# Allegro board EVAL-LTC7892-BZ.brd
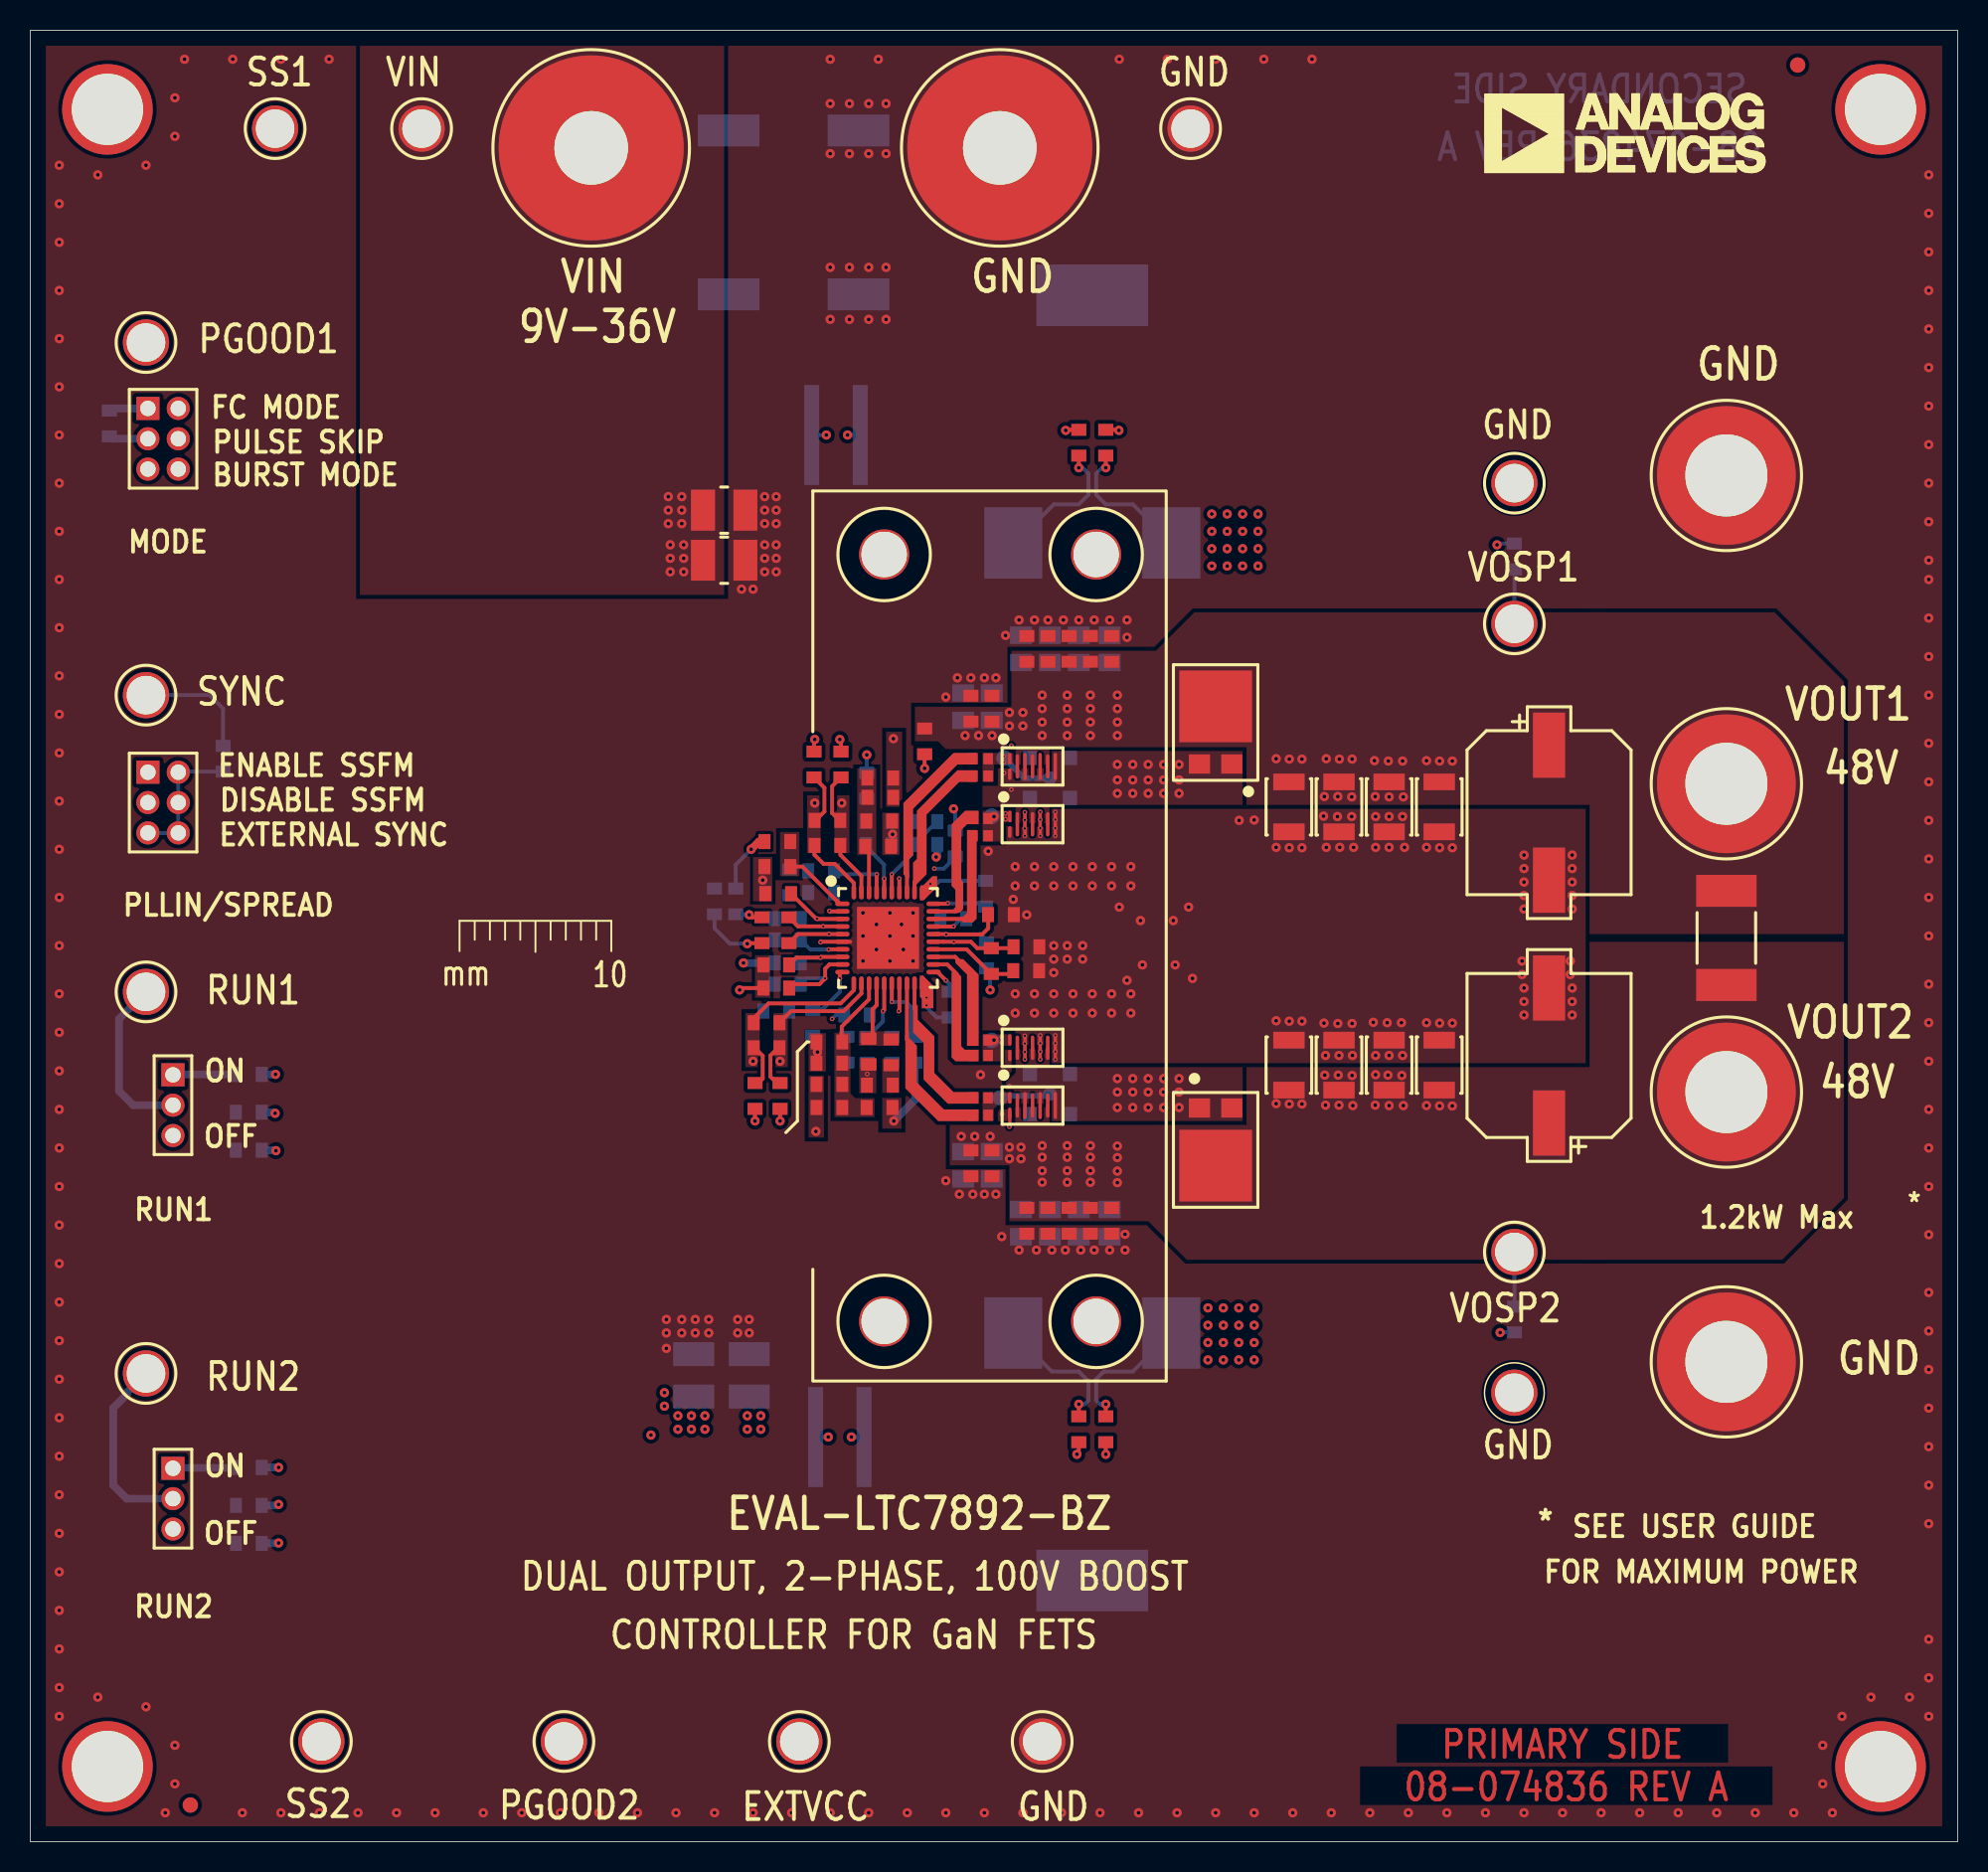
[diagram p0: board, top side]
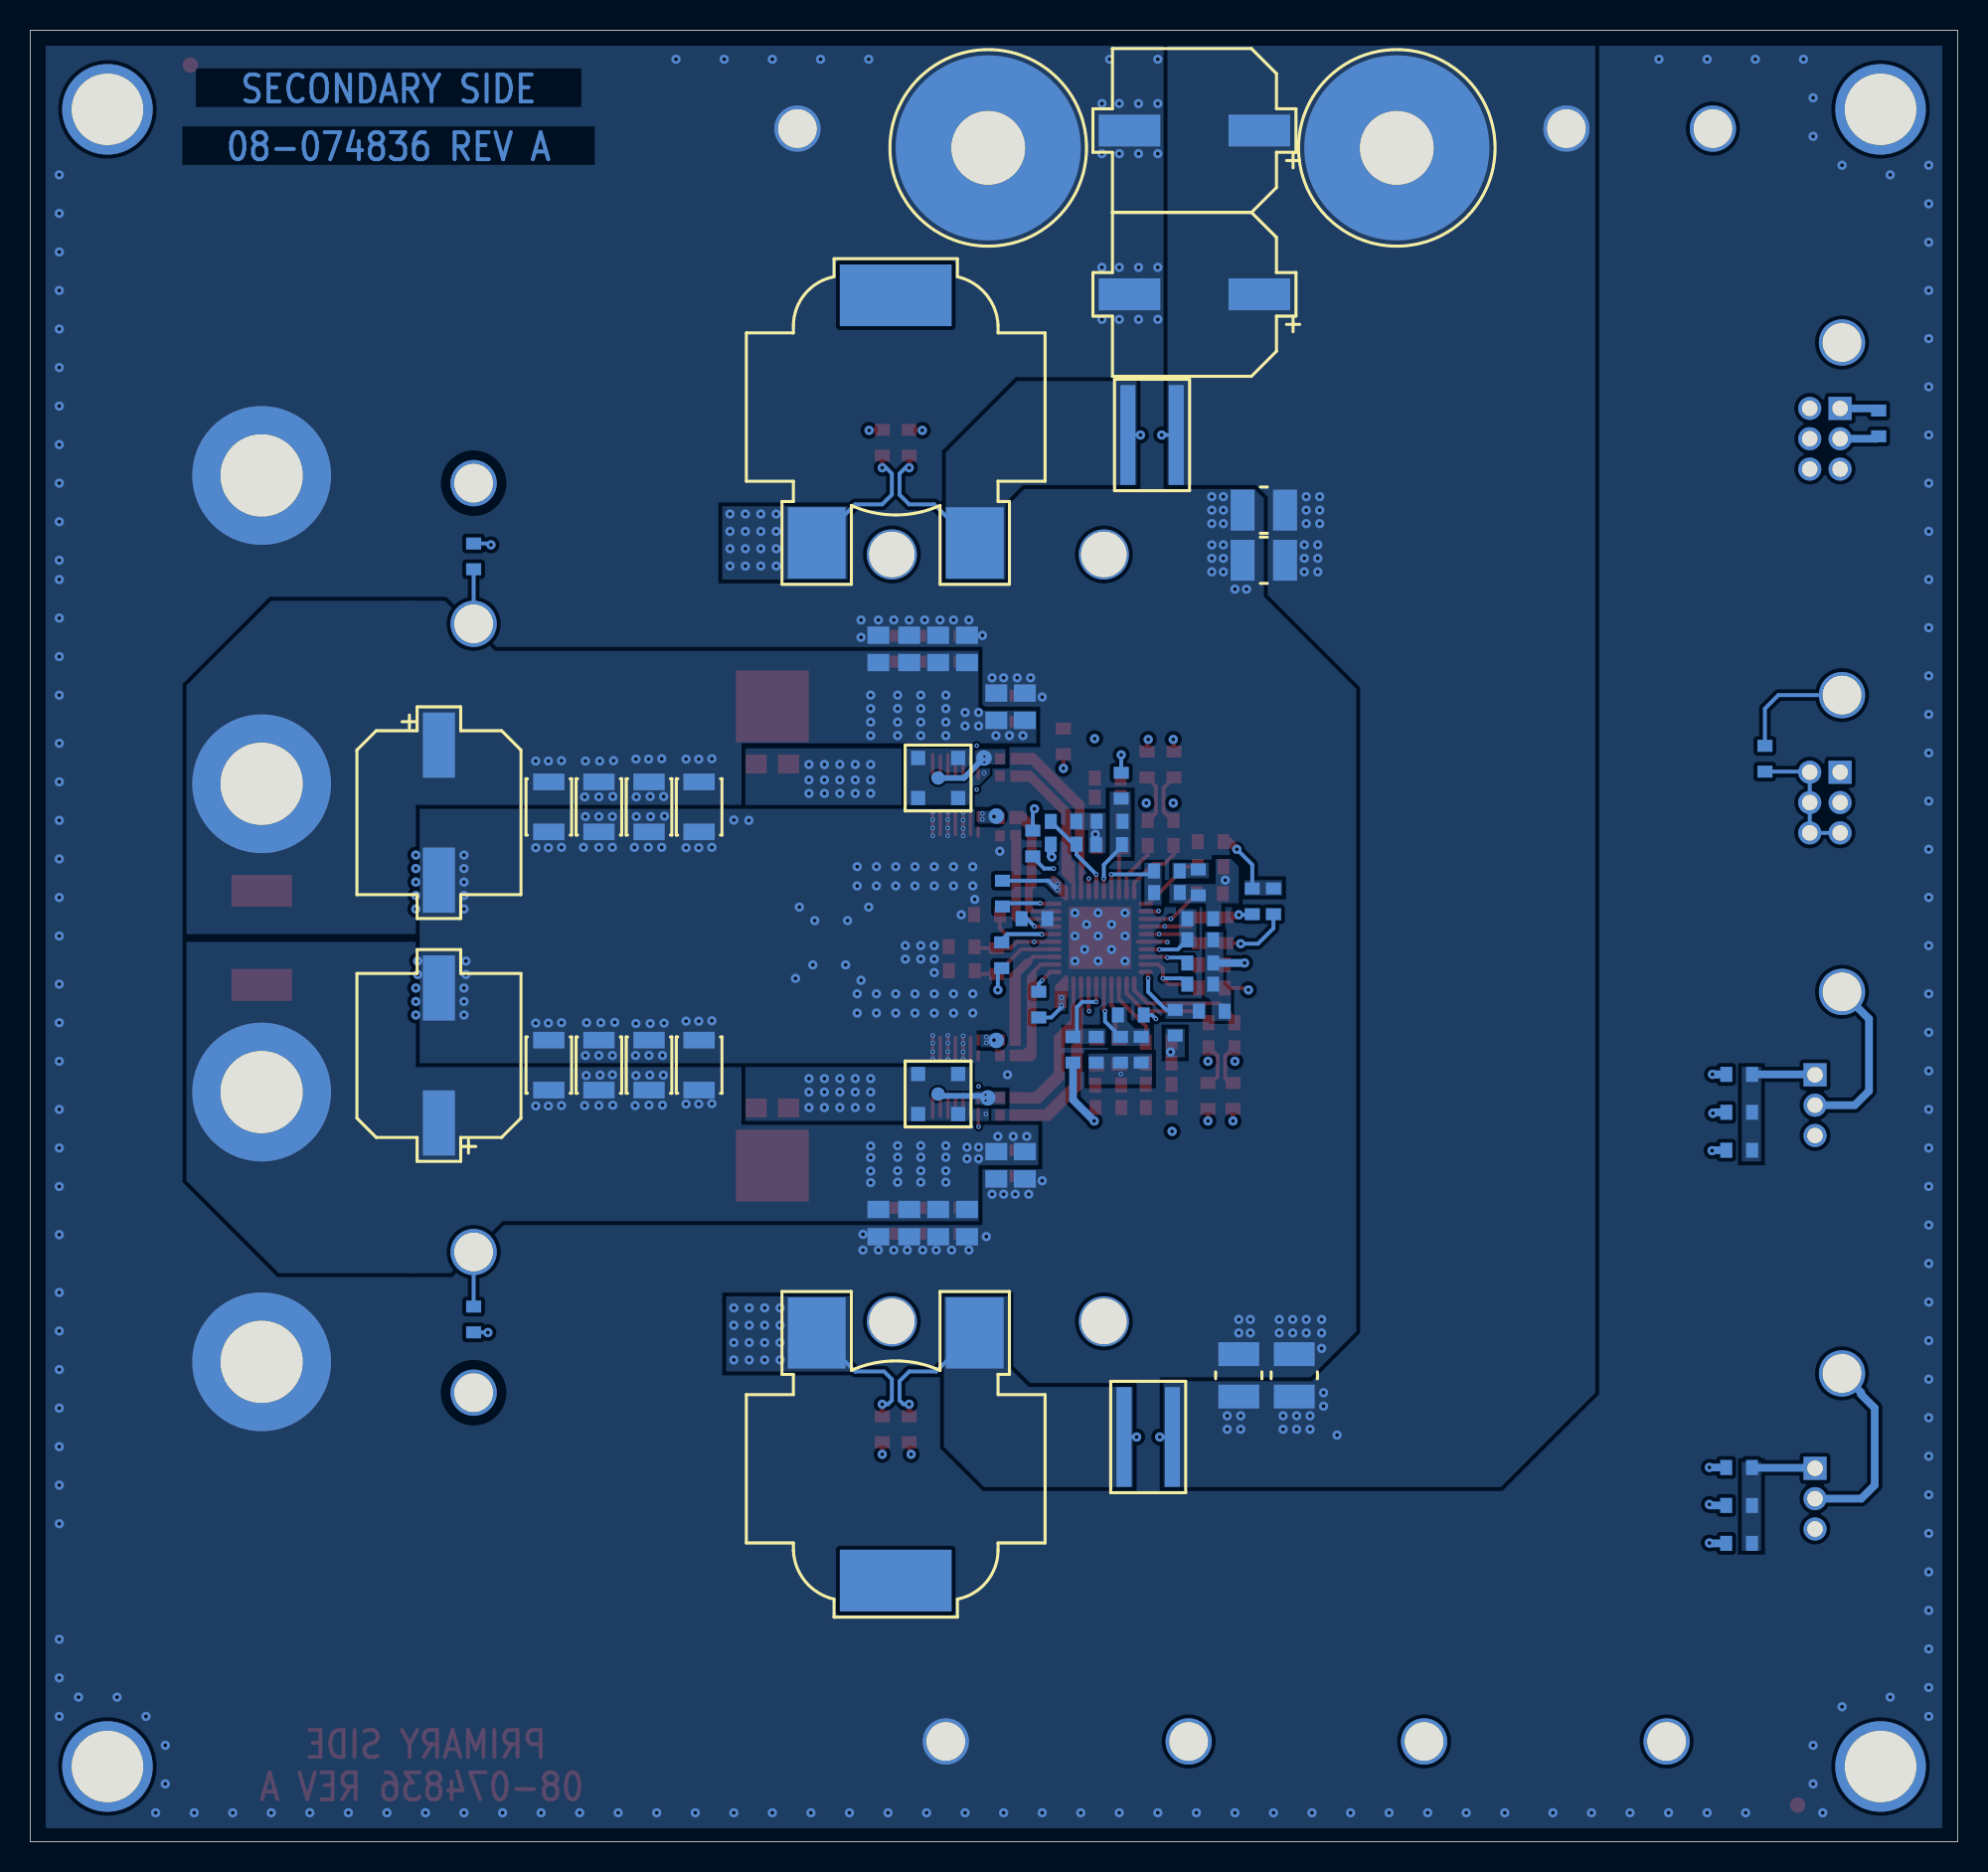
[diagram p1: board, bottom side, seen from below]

Outline 127 x 119.38 mm; copper layers: TOP, LAYER_2, LAYER_3, LAYER_4, LAYER_5, BOTTOM. Coordinates in mm from the lower left corner of the outline.
Outline path: 0,119.38 0,0 127,0 127,119.38 0,119.38

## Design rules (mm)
constraint set DEFAULT: min track width 0.254

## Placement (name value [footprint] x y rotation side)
C1  4.7uF  [C0603]  65.63 58.98 0 top
C2  4.7uF  [C0603]  65.62 57.4 0 top
C3  0.1uF  [C0603]  62.94 62.48 270 bottom
C4  0.1uF  [C0603]  60.55 55.17 270 bottom
C5  1000pF  [C0603]  48.51 52.32 0 top
C6  TBD0603  [C0603]  56.01 68.83 180 top
C7  1000pF  [C0603]  52.53 65.66 180 top
C8  TBD0603  [C0603]  55.87 65.6 0 top
C9  TBD0603  [C0603]  52.65 49.91 0 top
C10  1000pF  [C0603]  52.11 62.55 0 bottom
C11  TBD0603  [C0603]  55.24 52.07 270 top
C12  TBD0603  [C0603]  55.98 49.86 180 top
C13  TBD0603  [C0603]  52.65 52.7 180 top
C14  0.033uF  [C0603]  52.11 63.98 0 bottom
C15  TBD0603  [C0603]  55.17 52.2 270 bottom
C16  TBD0603  [C0603]  49.28 62.48 180 top
C17  0.1uF  [C0603]  55.88 67.24 0 bottom
C18  TBD0603  [C0603]  14.4 19.66 0 bottom
C19  0.22uF  [C0603]  65.66 78.61 90 top
C20  0.22uF  [C0603]  67.06 78.61 90 top
C21  0.22uF  [C0603]  68.45 78.61 90 top
C22  0.22uF  [C0603]  69.85 78.61 90 top
C23  0.22uF  [C0603]  71.25 78.61 90 top
C24  TBD0603  [C0603]  14.4 45.57 0 bottom
C25  0.1uF  [C0603]  60.83 60.83 180 bottom
C26  0.22uF  [C0603]  61.98 44.7 270 top
C27  0.22uF  [C0603]  63.37 44.7 270 top
C28  0.22uF  [C0603]  65.66 40.92 270 top
C29  0.22uF  [C0603]  67.06 40.92 270 top
C30  0.22uF  [C0603]  68.45 40.92 270 top
C31  0.22uF  [C0603]  69.85 40.92 270 top
C32  0.22uF  [C0603]  71.25 40.92 270 top
C33  0.22uF  [C0603]  61.98 74.68 90 top
C34  0.22uF  [C0603]  63.37 74.68 90 top
CIN1  150UF  [CPLSMSQ406H508]  50.29 101.98 0 bottom
CIN2  150UF  [CPLSMSQ406H508]  50.29 112.78 0 bottom
CIN3  10uF  [C1210-2]  45.72 84.45 0 top
CIN4  10uF  [C1210-2]  45.72 87.76 0 top
CIN5  10uF  [C1210-2]  45.72 84.45 0 bottom
CIN6  10uF  [C1210-2]  45.72 87.76 0 bottom
CIN7  10uF  [C1210-2]  47.37 30.73 90 bottom
CIN8  10uF  [C1210-2]  43.71 30.73 90 bottom
COUT1  10UF  [C1210H106]  89.53 51.18 90 top
COUT2  10UF  [C1210H106]  86.23 51.18 90 top
COUT3  68UF  [CPLSMSQ406H413]  100.08 51.82 90 bottom
COUT4  68UF  [CPLSMSQ406H413]  100.08 51.82 90 top
COUT5  68UF  [CPLSMSQ406H413]  100.08 67.82 270 bottom
COUT6  68UF  [CPLSMSQ406H413]  100.08 67.82 270 top
COUT7  10UF  [C1210H106]  89.53 68.2 270 top
COUT8  10UF  [C1210H106]  86.23 68.2 270 top
COUT9  1uF  [C0805]  61.47 74.8 90 bottom
COUT10  1uF  [C0805]  63.35 74.8 90 bottom
COUT11  10UF  [C1210H106]  89.53 68.2 270 bottom
COUT12  10UF  [C1210H106]  86.23 68.2 270 bottom
COUT13  1uF  [C0805]  71.12 40.77 270 bottom
COUT14  10UF  [C1210H106]  89.53 51.18 90 bottom
COUT15  1uF  [C0805]  67.18 40.77 270 bottom
COUT16  1uF  [C0805]  65.28 78.61 90 bottom
COUT17  1uF  [C0805]  67.18 78.61 90 bottom
COUT18  10UF  [C1210H106]  86.23 51.18 90 bottom
COUT19  1uF  [C0805]  69.09 78.61 90 bottom
COUT20  1uF  [C0805]  71.12 78.61 90 bottom
COUT21  1uF  [C0805]  69.09 40.77 270 bottom
COUT22  1uF  [C0805]  61.47 44.58 270 bottom
COUT23  1uF  [C0805]  63.35 44.58 270 bottom
COUT24  1uF  [C0805]  65.28 40.77 270 bottom
COUT25  10UF  [C1210H106]  82.93 68.2 270 top
COUT26  10UF  [C1210H106]  82.93 68.2 270 bottom
COUT27  10UF  [C1210H106]  92.84 68.2 270 top
COUT28  10UF  [C1210H106]  92.84 68.2 270 bottom
COUT29  10UF  [C1210H106]  82.93 51.18 90 top
COUT30  10UF  [C1210H106]  82.93 51.18 90 bottom
COUT31  10UF  [C1210H106]  92.84 51.18 90 top
COUT32  10UF  [C1210H106]  92.84 51.18 90 bottom
D1  SS10PH10-M3/86A  [TO-277A]  78.11 73.79 90 top
D2  SS10PH10-M3/86A  [TO-277A]  78.11 45.59 270 top
E1  2501-2-00-80-00-00-07-0  [CNMILLMAX2501]  35.16 6.6 0 top
E2  2501-2-00-80-00-00-07-0  [CNMILLMAX2501]  7.62 98.81 0 top
E3  2501-2-00-80-00-00-07-0  [CNMILLMAX2501]  25.78 112.9 0 top
E4  2501-2-00-80-00-00-07-0  [CNMILLMAX2501]  76.45 112.9 0 top
E5  2501-2-00-80-00-00-07-0  [CNMILLMAX2501]  97.79 38.86 0 top
E6  2501-2-00-80-00-00-07-0  [CNMILLMAX2501]  97.79 80.26 270 top
E7  2501-2-00-80-00-00-07-0  [CNMILLMAX2501]  97.79 29.59 0 top
E8  2501-2-00-80-00-00-07-0  [CNMILLMAX2501]  97.79 89.53 270 top
E9  2501-2-00-80-00-00-07-0  [CNMILLMAX2501]  19.18 6.6 0 top
E10  2501-2-00-80-00-00-07-0  [CNMILLMAX2501]  7.62 75.56 0 top
E11  2501-2-00-80-00-00-07-0  [CNMILLMAX2501]  16.13 112.9 0 top
E12  2501-2-00-80-00-00-07-0  [CNMILLMAX2501]  50.67 6.6 0 top
E13  2501-2-00-80-00-00-07-0  [CNMILLMAX2501]  66.67 6.6 0 top
E16  2501-2-00-80-00-00-07-0  [CNMILLMAX2501]  7.62 56.01 180 top
E17  2501-2-00-80-00-00-07-0  [CNMILLMAX2501]  7.62 30.86 0 top
J1  KFH-032-10ET  [CNPEMKFH-032]  36.96 111.63 0 top
J2  KFH-032-10ET  [CNPEMKFH-032]  63.88 111.63 0 top
J3  575-4  [CNBANANAD312LD203]  111.76 49.4 0 top
J4  575-4  [CNBANANAD312LD203]  111.76 31.62 0 top
J5  575-4  [CNBANANAD312LD203]  111.76 69.72 270 top
J6  575-4  [CNBANANAD312LD203]  111.76 90.04 270 top
J7  0734152063  [CNSMASQ136H203]  67.18 70.1 180 bottom
J8  0734152063  [CNSMASQ136H203]  67.18 49.28 180 bottom
L1  3.6UH  [LSML755W365H510]  69.98 94.55 180 bottom
L2  3.6UH  [LSML755W365H510]  69.98 24.57 0 bottom
NOREF  -  [unnamed]  5.08 4.95 0 top
NOREF#2  -  [#2]  45.59 139.7 0 top
NOREF#3  -  [#2]  176.53 315.6 0 top
NOREF#4  -  [#2]  133.58 119.27 0 top
NOREF#5  -  [#2]  -1.45 -27.73 0 top
NOREF#6  -  [unnamed]  121.92 4.95 0 top
NOREF#7  -  [unnamed]  121.92 114.17 0 top
NOREF#8  -  [#2]  0 0 90 top
NOREF#9  -  [unnamed]  10.54 2.41 0 top
NOREF#10  -  [#2]  -160.27 -186.82 0 top
NOREF#11  -  [#2]  265.39 236.48 0 top
NOREF#12  -  [#2]  0 119.38 0 top
NOREF#13  -  [unnamed]  116.46 117.09 0 top
NOREF#14  -  [#2]  104.65 305.56 0 top
NOREF#15  -  [#2]  -23.37 116.09 0 top
NOREF#16  -  [#2]  4.57 -22.12 0 top
NOREF#17  -  [#2]  127.76 -10.8 0 top
NOREF#18  -  [#2]  271.14 172.97 0 top
NOREF#19  -  [#2]  25.26 95.38 270 top
NOREF#20  -  [#2]  0 0 0 top
NOREF#21  -  [#2]  -200.81 -186.59 0 top
NOREF#22  -  [#2]  96.37 308.2 0 top
NOREF#23  -  [#2]  100.48 117.09 0 top
NOREF#24  -  [#2]  -84.58 -68.07 0 top
NOREF#25  -  [#2]  0 0 90 top
NOREF#26  -  [unnamed]  5.08 114.17 0 top
P1  TMM-103-02-L-D  [CNTHMHDR2X3L236W155H225]  7.75 94.46 270 top
P2  TMM-103-02-L-D  [CNTHMHDR2X3L236W155H225]  7.75 70.48 270 top
P3  TMM-103-02-G-S  [CNTHMHDR1X3L236W78H215]  9.4 50.54 270 top
P4  TMM-103-02-G-S  [CNTHMHDR1X3L236W78H215]  9.4 24.61 270 top
P10  9774010243R  [CNWURTH9774010243R]  70.23 84.84 0 top
P11  9774010243R  [CNWURTH9774010243R]  56.26 84.84 0 top
P12  9774010243R  [CNWURTH9774010243R]  70.23 34.29 0 top
P13  9774010243R  [CNWURTH9774010243R]  56.26 34.29 0 top
Q1  EPC2218  [DIE8_3_5X1_95_A]  66.04 70.87 0 top
Q2  EPC2218  [DIE8_3_5X1_95_A]  66.04 67.06 0 top
Q3  EPC2218  [DIE8_3_5X1_95_A]  66.04 52.32 0 top
Q4  EPC2218  [DIE8_3_5X1_95_A]  66.04 48.51 0 top
R1  1MEG  [R0603]  45.09 61.98 270 bottom
R2  0  [R0603]  60.94 65.79 270 bottom
R3  0  [R0603]  49.15 57.78 180 top
R4  TBD0603  [R0603]  58.93 72.52 270 top
R5  1MEG  [R0603]  46.48 61.98 270 bottom
R6  2  [R0402]  62.61 71.37 180 top
R7  2  [R0402]  62.61 47.88 0 top
R8  1  [R0402]  62.61 70.23 180 top
R9  1  [R0402]  62.61 49.02 0 top
R11  0  [R0603]  55.24 52.07 270 top
R12  51  [R0603]  97.79 34.42 270 bottom
R13  2  [R0402]  62.61 66.29 180 top
R14  2  [R0402]  62.61 52.83 0 top
R15  1  [R0402]  62.61 67.44 180 top
R16  1  [R0402]  62.61 51.82 0 top
R17  51  [R0603]  97.79 84.71 90 bottom
R18  1MEG  [R0603]  56.01 70.1 180 top
R19  25.5K  [R0603]  55.94 67.27 0 top
R20  1.4K  [R0603]  50.04 63.22 90 bottom
R21  TBD0603  [R0603]  56.72 52.02 270 top
R22  0  [R0603]  55.96 48.39 0 top
R23  TBD0603  [R0603]  52.65 48.39 0 top
R24  49.9  [R0603]  49.4 49.15 90 top
R25  0  [R0603]  47.75 49.15 90 top
R26  TBD0603  [R0603]  70.87 27.18 270 top
R27  TBD0603  [R0603]  69.09 27.18 270 top
R28  0  [R0603]  51.64 70.99 270 top
R29  49.9  [R0603]  53.42 70.99 270 top
R30  TBD0603  [R0603]  69.09 92.2 90 top
R31  TBD0603  [R0603]  70.87 92.2 90 top
R32  TBD0603  [R0603]  52.65 51.31 180 top
R33  TBD0603  [R0603]  48.51 53.97 180 top
R34  TBD0603  [R0603]  52.53 67.31 180 top
R35  0  [R0603]  63.32 58.04 90 top
R36  24.9K  [R0603]  49.15 56.26 180 top
R37  75K  [R0603]  49.23 64.26 0 top
R38  TBD0603  [R0603]  49.23 65.91 180 top
R40  TBD0603  [R0603]  49.91 56.52 180 bottom
R41  15K  [R0603]  51.56 53.97 270 bottom
R42  TBD0603  [R0603]  49.15 54.74 180 bottom
R43  TBD0603  [R0603]  58.91 67.24 180 bottom
R44  TBD0603  [R0603]  58.91 65.74 0 bottom
R45  TBD0603  [R0603]  49.91 57.91 180 bottom
R46  0  [R0603]  63.96 61.1 0 top
R47  0  [R0603]  58.29 52.2 90 bottom
R48  TBD0603  [R0603]  56.77 52.2 90 bottom
R49  1K  [R0603]  12.7 71.37 270 bottom
R50  TBD0603  [R0603]  54.48 54.48 180 bottom
R51  0  [R0603]  53.8 52.2 270 bottom
R52  0  [R0603]  55.12 69.6 270 bottom
R53  TBD0603  [R0603]  55.92 65.72 0 bottom
R54  TBD0603  [R0603]  49.91 59.44 180 bottom
R55  0  [R0603]  49.91 60.83 180 bottom
R56  1MEG  [R0603]  14.4 24.66 0 bottom
R57  100K  [R0603]  5.21 93.47 270 bottom
R58  TBD0603  [R0603]  14.4 22.16 0 bottom
R60  0  [R0603]  48.21 60.07 270 top
R61  TBD0603  [R0603]  62.99 58.42 270 bottom
R62  1MEG  [R0603]  14.4 50.57 180 bottom
R63  158K  [R0603]  14.4 48.07 0 bottom
R64  0  [R0603]  49.99 60.07 270 top
R67  0  [R2512H35]  111.76 59.56 270 top
RS1  0.002  [R1225H28]  53.09 92.71 0 bottom
RS2  0.002  [R1225H28]  53.34 26.67 180 bottom
U1  LTC7892AUJM#TRPBF  [QFN40_6X6_PAD4_1X4_1_05-08-1681]  56.52 59.56 270 top

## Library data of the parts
C1 C2 = CAP: Tolerance: 10; User Part Number: UPN; alternate symbols: (C0603); part number: CAP_SM-4.7UF,25V,10,E035948,C0603; tolerance: 10
C3 C4 C17 = CAP: Tolerance: 10; User Part Number: UPN; alternate symbols: (C0603); part number: CAP_SM-0.1UF,25V,10,E013746,C0603; tolerance: 10
C5 C7 = CAP: Tolerance: 10; User Part Number: UPN; alternate symbols: (C0603); part number: CAP_SM-1000PF,25V,10,E042649,C0603; tolerance: 10
C6 C8 C9 C11-C13 C15 C16 C18 C24 = CAP: User Part Number: UPN; alternate symbols: (C0603); part number: CAP_SM-TBD0603,TBD0603,TBD0603,E000382,C0603
C10 = CAP: Tolerance: 10; User Part Number: UPN; alternate symbols: (C0603); part number: CAP_SM-1000PF,50V,10,E013782,C0603; tolerance: 10
C14 = CAP: Tolerance: 5; User Part Number: UPN; alternate symbols: (C0603); part number: CAP_SM-0.033UF,50V,5,E024637,C0603; tolerance: 5
C19-C23 C26-C34 = CAP: Tolerance: 10; User Part Number: UPN; alternate symbols: (C0603); part number: CAP_SM-0.22UF,100V,10,E031432,C0603; tolerance: 10
C25 = CAP: Tolerance: 10; User Part Number: UPN; alternate symbols: (C0603); part number: CAP_SM-0.1UF,100V,10,E024908,C0603; tolerance: 10
CIN1 CIN2 = CAPP: User Part Number: UPN; Tolerance: 20; alternate symbols: (CPLSMSQ406H508); part number: CAPP_SM-150UF,50V,20,E061932,CPLSMSQ406H508; tolerance: 20
CIN3-CIN8 = CAP: Tolerance: 10; User Part Number: UPN; alternate symbols: (C1210-2); part number: CAP_SM-10UF,50V,10,E022361,C1210-2; tolerance: 10
COUT1 COUT2 COUT7 COUT8 COUT11 COUT12 COUT14 COUT18 COUT25-COUT32 = CAP: Tolerance: 10; User Part Number: UPN; alternate symbols: (C1210H106); part number: CAP_SM-10UF,100V,10,E044329,C1210H106; tolerance: 10
COUT3-COUT6 = CAPP: User Part Number: UPN; Tolerance: 20; alternate symbols: (CPLSMSQ406H413); part number: CAPP_SM-68UF,63V,20,E046041,CPLSMSQ406H413; tolerance: 20
COUT9 COUT10 COUT13 COUT15-COUT17 COUT19-COUT24 = CAP: User Part Number: UPN; Tolerance: 10; alternate symbols: (C0805); part number: CAP_SM-1UF,100V,10,E014208,C0805; tolerance: 10
D1 D2 = DIO3P_V7: User Part Number: UPN; Tolerance: N/A; alternate symbols: (TO-277A); part number: DIO3P_V7_SM-SS10PH10-M3/86A,100V,N/A,E057759,TO-277A; tolerance: N/A
E1-E13 E16 E17 = CNTP1P: User Part Number: UPN; Tolerance: N/A; alternate symbols: (CNMILLMAX2501); part number: CNTP1P_TH-2501-2-00-80-00-00-07-0,E031108,CNMILLMAX2501; tolerance: N/A
J1 J2 = CN1P: User Part Number: UPN; Tolerance: N/A; alternate symbols: (CNPEMKFH-032); part number: CN1P_TH-KFH-032-10ET,E039893,CNPEMKFH-032; tolerance: N/A
J3-J6 = CNTP1P: Tolerance: N/A; User Part Number: UPN; alternate symbols: (CNBANANAD312LD203); part number: CNTP1P_TH-575-4,E012555,CNBANANAD312LD203; tolerance: N/A
J7 J8 = CNBNC5P: Tolerance: N/A; User Part Number: UPN; alternate symbols: (CNSMASQ136H203); part number: CNBNC5P_SM-0734152063,E050157,CNSMASQ136H203; tolerance: N/A
L1 L2 = IND: User Part Number: UPN; Tolerance: 20; alternate symbols: (LSML755W365H510); part number: IND_SM-3.6UH,20,E061762,LSML755W365H510; tolerance: 20
P1 P2 = CN6P_ODD_EVEN: User Part Number: UPN; Tolerance: N/A; alternate symbols: (CNTHMHDR2X3L236W155H225); part number: CN6P_ODD_EVEN_TH-TMM-103-02-L-D,E043044,CNTHMHDR2X3L236W155H225; tolerance: N/A
P3 P4 = CN3P: User Part Number: UPN; Tolerance: N/A; alternate symbols: (CNTHMHDR1X3L236W78H215); part number: CN3P_TH-TMM-103-02-G-S,E059946,CNTHMHDR1X3L236W78H215; tolerance: N/A
P10-P13 = CN1P: Tolerance: N/A; User Part Number: UPN; alternate symbols: (CNWURTH9774010243R); part number: CN1P_TH-9774010243R,E060235,CNWURTH9774010243R; tolerance: N/A
Q1-Q4 = TRANNGANFET8P: Tolerance: N/A; User Part Number: UPN; alternate symbols: (DIE8_3_5X1_95_A); part number: TRANNGANFET8P_SM-EPC2218,E058016,DIE8_3_5X1_95_A; tolerance: N/A
R1 R5 R18 R56 R62 = RES: User Part Number: UPN; Tolerance: 1; alternate symbols: (R0603); part number: RES_SM-1MEG,E030873,1/10W,1,R0603; tolerance: 1
R2 R3 R11 R22 R25 R28 R35 R46 R47 R51 R52 R55 R60 R64 = RES: User Part Number: UPN; Tolerance: JUMPER; alternate symbols: (R0603); part number: RES_SM-0,E007502,1/10W,JUMPER,R0603; tolerance: JUMPER
R4 R21 R23 R26 R27 R30-R34 R38 R40 R42-R45 R48 R50 R53 R54 R58 R61 = RES: User Part Number: UPN; alternate symbols: (R0603); part number: RES_SM-TBD0603,E004050,TBD0603,TBD0603,R0603
R6 R7 R13 R14 = RES: User Part Number: UPN; Tolerance: 1; alternate symbols: (R0402); part number: RES_SM-2,E022716,1/16W,1,R0402; tolerance: 1
R8 R9 R15 R16 = RES: User Part Number: UPN; alternate symbols: (R0402); part number: RES_SM-1,E062941,1/16W,1,R0402
R12 R17 = RES: User Part Number: UPN; Tolerance: 1; alternate symbols: (R0603); part number: RES_SM-51,E010181,1/10W,1,R0603; tolerance: 1
R19 = RES: User Part Number: UPN; Tolerance: 1; alternate symbols: (R0603); part number: RES_SM-25.5K,E011039,1/10W,1,R0603; tolerance: 1
R20 = RES: User Part Number: UPN; Tolerance: 1; alternate symbols: (R0603); part number: RES_SM-1.4K,E048984,1/10W,1,R0603; tolerance: 1
R24 R29 = RES: User Part Number: UPN; Tolerance: 1; alternate symbols: (R0603); part number: RES_SM-49.9,E003673,1/10W,1,R0603; tolerance: 1
R36 = RES: User Part Number: UPN; Tolerance: 1; alternate symbols: (R0603); part number: RES_SM-24.9K,E030453,1/10W,1,R0603; tolerance: 1
R37 = RES: User Part Number: UPN; Tolerance: 1; alternate symbols: (R0603); part number: RES_SM-75K,E012707,1/10W,1,R0603; tolerance: 1
R41 = RES: User Part Number: UPN; Tolerance: 0.1; alternate symbols: (R0603); part number: RES_SM-15K,E003957,1/10W,0.1,R0603; tolerance: 0.1
R49 = RES: User Part Number: UPN; Tolerance: 1; alternate symbols: (R0603); part number: RES_SM-1K,E003678,1/10W,1,R0603; tolerance: 1
R57 = RES: User Part Number: UPN; Tolerance: 1; alternate symbols: (R0603); part number: RES_SM-100K,E010279,1/10W,1,R0603; tolerance: 1
R63 = RES: User Part Number: UPN; Tolerance: 1; alternate symbols: (R0603); part number: RES_SM-158K,E045514,1/10W,1,R0603; tolerance: 1
R67 = RES: User Part Number: UPN; Tolerance: JUMPER; alternate symbols: (R2512H35); part number: RES_SM-0,E050944,N/A,JUMPER,R2512H35; tolerance: JUMPER
RS1 RS2 = RES: User Part Number: UPN; Tolerance: 2; alternate symbols: (R1225H28); part number: RES_SM-0.002,E068091,3W,2,R1225H28; tolerance: 2
U1 = ADLTC7892_V2: User Part Number: UPN; Tolerance: N/A; alternate symbols: (QFN40_6X6_PAD4_1X4_1_05-08-1681); part number: ADLTC7892_V2_SM-LTC7892AUJM#TRPBF,E064946,QFN40_6X6_PAD4_1X4_1_05-08-1681; tolerance: N/A

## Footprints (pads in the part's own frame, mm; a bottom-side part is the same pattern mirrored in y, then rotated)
C0603
  rect 0.787x0.991 smd: 1(-0.85,0) 2(0.85,0)
C0805
  rect 1.143x1.448 smd: 1(-0.9,0) 2(0.9,0)
C1210-2
  rect 1.575x2.692 smd: 1(-1.397,0) 2(1.397,0)
C1210H106
  rect 1.092x2.057 smd: 1(-1.646,0) 2(1.646,0)
CNBANANAD312LD203
  round 9.144 hole 5.41: 1(0,0)
CNMILLMAX2501
  round 3.048 hole 2.54: 1(0,0)
CNPEMKFH-032
  round 12.192 hole 4.851: 1(0,0)
CNSMASQ136H203
  round 0.889 smd: 1(0,0)
  rect 0.94x0.94 smd: 2(-1.32,-1.32) 3(1.32,-1.32) 4(1.32,1.32) 5(-1.32,1.32)
CNTHMHDR1X3L236W78H215
  rect 1.524x1.524 hole 1.016: 1(0,0)
  round 1.524 hole 1.016: 2(2,0) 3(4,0)
CNTHMHDR2X3L236W155H225
  rect 1.524x1.524 hole 1.016: 1(0,0)
  round 1.524 hole 1.016: 2(0,2) 3(2,0) 4(2,2) 5(4,0) 6(4,2)
CNWURTH9774010243R
  round 3.302 hole 2.997 unplated: (0,0)
  round 0 smd: 1(0,0)
CPLSMSQ406H413
  rect 4.293x2.108 smd: N(4.45,0) P(-4.45,0)
CPLSMSQ406H508
  rect 4.064x2.108 smd: N(4.277,0) P(-4.277,0)
DIE8_3_5X1_95_A
  oval 0.229x0.762 smd: 1(-1.5,0.513) 2(-1.5,-0.513)
  oval 0.229x1.6 smd: 3(-1,0) 5(0,0) 7(1,0)
  oval 0.229x1.778 smd: 4(-0.5,0) 6(0.5,0) 8(1.5,0)
LSML755W365H510
  rect 7.366x4.064 smd: (0,7.366)
  rect 3.81x4.699 smd: 1(-5.207,-8.954) 2(5.207,-8.954)
QFN40_6X6_PAD4_1X4_1_05-08-1681
  oval 0.305x0.94 smd: 1(-2.25,-3.005) 2(-1.75,-3.005) 3(-1.25,-3.005) 4(-0.75,-3.005) 5(-0.25,-3.005) 6(0.25,-3.005) 7(0.75,-3.005) 8(1.25,-3.005) 9(1.75,-3.005) 10(2.25,-3.005) 21(2.25,3.005) 22(1.75,3.005) 23(1.25,3.005) 24(0.75,3.005) 25(0.25,3.005) 26(-0.25,3.005) 27(-0.75,3.005) 28(-1.25,3.005) 29(-1.75,3.005) 30(-2.25,3.005)
  oval 0.94x0.305 smd: 11(3.005,-2.25) 12(3.005,-1.75) 13(3.005,-1.25) 14(3.005,-0.75) 15(3.005,-0.25) 16(3.005,0.25) 17(3.005,0.75) 18(3.005,1.25) 19(3.005,1.75) 20(3.005,2.25) 31(-3.005,2.25) 32(-3.005,1.75) 33(-3.005,1.25) 34(-3.005,0.75) 35(-3.005,0.25) 36(-3.005,-0.25) 37(-3.005,-0.75) 38(-3.005,-1.25) 39(-3.005,-1.75) 40(-3.005,-2.25)
  rect 4.089x4.089 smd: 41(0,0)
R0402
  rect 0.635x0.737 smd: 1(-0.5,0) 2(0.5,0)
R0603
  rect 0.787x0.991 smd: 1(-0.85,0) 2(0.85,0)
R1225H28
  rect 0.991x6.579 smd: 1(-1.595,0) 2(1.595,0)
R2512H35
  rect 2.108x3.988 smd: 1(-3.104,0) 2(3.104,0)
TO-277A
  rect 1.27x1.397 smd: 1(-2.765,-1.065) 2(-2.765,1.065)
  rect 4.724x4.801 smd: 3(1.038,0)
unnamed
  round 5.969 hole 4.699 unplated: (0,0)

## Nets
GND_POWER: C1.2(N2) C2.2(N2) C19.2(N2) C20.2(N2) C21.2(N2) C22.2(N2) C23.2(N2) C25.2(N2) C26.2(N2) C27.2(N2) C28.2(N2) C29.2(N2) C30.2(N2) C31.2(N2) C32.2(N2) C33.2(N2) C34.2(N2) CIN1.N(N2) CIN2.N(N2) CIN3.2(N2) CIN4.2(N2) CIN5.2(N2) CIN6.2(N2) CIN7.2(N2) CIN8.2(N2) COUT1.2(N2) COUT2.2(N2) COUT3.N(N2) COUT4.N(N2) COUT5.N(N2) COUT6.N(N2) COUT7.2(N2) COUT8.2(N2) COUT9.2(N2) COUT10.2(N2) COUT11.2(N2) COUT12.2(N2) COUT13.2(N2) COUT14.2(N2) COUT15.2(N2) COUT16.2(N2) COUT17.2(N2) COUT18.2(N2) COUT19.2(N2) COUT20.2(N2) COUT21.2(N2) COUT22.2(N2) COUT23.2(N2) COUT24.2(N2) COUT25.2(N2) COUT26.2(N2) COUT27.2(N2) COUT28.2(N2) COUT29.2(N2) COUT30.2(N2) COUT31.2(N2) COUT32.2(N2) E4.1(N1) E7.1(N1) E8.1(N1) E13.1(N1) J2.1(N1) J4.1(N1) J6.1(N1) Q2.2 Q2.4 Q2.6 Q2.8(S4) Q3.2 Q3.4 Q3.6 Q3.8(S4) R46.2(N2) U1.41
GND_SIGNAL: C8.2(N2) C10.1 C11.2(N2) C12.2(N2) C13.2(N2) C15.2(N2) C16.2(N2) C17.2(N2) C18.2(N2) C24.2(N2) P1.5 P2.3 P3.3(N3) P4.3(N3) R3.2(N2) R11.2(N2) R19.2(N2) R20.1 R32.2(N2) R36.2(N2) R37.1 R41.2(N2) R43.2(N2) R48.1 R51.2(N2) R53.2(N2) R55.2(N2) R58.2(N2) R63.2(N2) U1.6
VIN: CIN1.P CIN2.P CIN3.1 CIN4.1 CIN5.1 CIN6.1 CIN7.1 CIN8.1 E3.1(N1) J1.1(N1) R2.1 R25.1 R28.1 R56.2(N2) R62.1 RS1.1 RS2.2(N2)
EXTVCC: R46.1 R61.1 U1.26
INTVCC: C1.1 P1.1 P2.1 R1.1 R5.1 R22.2(N2) R35.2(N2) R38.2(N2) R40.2(N2) R42.2(N2) R44.2(N2) R45.2(N2) R47.1 R54.2(N2) R57.1 U1.25
PGOOD1: E2.1(N1) R5.2(N2) R60.1 U1.34
PGOOD2: E1.1(N1) R1.2(N2) R60.2(N2) U1.17
RUN1: E16.1(N1) P3.2 R64.1 U1.4
RUN2: E17.1(N1) P4.2 R64.2(N2) U1.5
SENSE1+: C7.2(N2) R28.2(N2) R30.2(N2) R34.2(N2) U1.40
SENSE1-: C7.1 R29.2(N2) R31.2(N2) R34.1 U1.39
SENSE2+: C5.1 R25.2(N2) R27.2(N2) R33.2(N2) U1.11
SENSE2-: C5.2(N2) R24.2(N2) R26.2(N2) R33.1 U1.12
UNNAMED_2_ADLTC7892V2_I690_BGDN1: R15.2(N2) U1.29
UNNAMED_2_ADLTC7892V2_I690_BGDN2: R16.1 U1.22
UNNAMED_2_ADLTC7892V2_I690_BGUP1: R13.2(N2) U1.28
UNNAMED_2_ADLTC7892V2_I690_BGUP2: R14.1 U1.23
UNNAMED_2_ADLTC7892V2_I690_BOOST1: C3.2(N2) U1.30
UNNAMED_2_ADLTC7892V2_I690_BOOST2: C4.1 U1.21
UNNAMED_2_ADLTC7892V2_I690_DRVCC: C2.1 R35.1 U1.24
UNNAMED_2_ADLTC7892V2_I690_DRVSET: R3.1 R45.1 U1.8
UNNAMED_2_ADLTC7892V2_I690_DRVUV: R54.1 R55.1 U1.7
UNNAMED_2_ADLTC7892V2_I690_DTCA: R36.1 R40.1 U1.9
UNNAMED_2_ADLTC7892V2_I690_DTCB: R41.1 R42.1 U1.10
UNNAMED_2_ADLTC7892V2_I690_FREQ: R37.2(N2) R38.1 U1.1
UNNAMED_2_ADLTC7892V2_I690_ILIM: R47.2(N2) R48.2(N2) U1.16
UNNAMED_2_ADLTC7892V2_I690_ITH1: C10.2(N2) C14.2(N2) U1.37
UNNAMED_2_ADLTC7892V2_I690_ITH2: C11.1 R11.1 R21.1 U1.14
UNNAMED_2_ADLTC7892V2_I690_MODE: P1.2 P1.4 P1.6(N6) U1.2
UNNAMED_2_ADLTC7892V2_I690_SS2: C15.1 R50.1 R51.1 U1.15
UNNAMED_2_ADLTC7892V2_I690_SW1: C3.1 D1.1 D1.2 J7.2 J7.3 J7.4 J7.5(SH4) L1.1 Q1.2 Q1.4 Q1.6 Q1.8(S4) Q2.3 Q2.5 Q2.7 R31.1 U1.31
UNNAMED_2_ADLTC7892V2_I690_SW2: C4.2(N2) D2.1 D2.2 J8.2 J8.3 J8.4 J8.5(SH4) L2.2(N2) Q3.3 Q3.5 Q3.7 Q4.2 Q4.4 Q4.6 Q4.8(S4) R26.1 U1.20
UNNAMED_2_ADLTC7892V2_I690_TGDN1: R8.2(N2) U1.32
UNNAMED_2_ADLTC7892V2_I690_TGDN2: R9.1 U1.19
UNNAMED_2_ADLTC7892V2_I690_TGUP1: R6.2(N2) U1.33
UNNAMED_2_ADLTC7892V2_I690_TGUP2: R7.1 U1.18
UNNAMED_2_ADLTC7892V2_I690_VBIAS: C25.1 R2.2(N2) R4.2(N2) U1.27
UNNAMED_2_ADLTC7892V2_I690_VPRG1: R43.1 R44.1 U1.35(VPRG1)
UNNAMED_2_CAP_I201_N1: C16.1 P2.2 P2.4 P2.5 P2.6(N6) R49.2(N2) U1.3
UNNAMED_2_CAP_I211_N1: C17.1 R52.2(N2) R53.1 U1.36
UNNAMED_2_CAP_I552_N1: C12.1 R21.2(N2)
UNNAMED_2_CAP_I715_N1: C14.1 R20.2(N2)
UNNAMED_2_CAP_I718_N1: C24.1 P3.1 R62.2(N2) R63.1
UNNAMED_2_CAP_I719_N1: C18.1 P4.1 R56.1 R58.1
UNNAMED_2_CN6PODDEVEN_I358_N3: P1.3 R57.2(N2)
UNNAMED_2_CNBNC5P_I602_CNTR: J7.1 Q1.1 R6.1 R8.1
UNNAMED_2_CNBNC5P_I603_CNTR: J8.1 Q4.1 R7.2(N2) R9.2(N2)
UNNAMED_2_CNTP1P_I84_N1: E10.1(N1) R49.1
UNNAMED_2_CNTP1P_I85_N1: E11.1(N1) R52.1
UNNAMED_2_CNTP1P_I261_N1: E12.1(N1) R61.2(N2)
UNNAMED_2_CNTP1P_I280_N1: E9.1(N1) R50.2(N2)
UNNAMED_2_IND_I545_N2: L1.2(N2) R29.1 R30.1 RS1.2(N2)
UNNAMED_2_IND_I546_N1: L2.1 R24.1 R27.1 RS2.1
UNNAMED_2_RES_I628_N1: Q2.1 R13.1 R15.1
UNNAMED_2_RES_I641_N2: Q3.1 R14.2(N2) R16.2(N2)
VFB1: C6.2(N2) C8.1 R18.2(N2) R19.1 U1.38
VFB2: C9.2(N2) C13.1 R22.1 R23.2(N2) R32.1 U1.13
VOSP1: C6.1 E6.1(N1) R17.1 R18.1
VOSP2: C9.1 E5.1(N1) R12.1 R23.1
VOUT1: C19.1 C20.1 C21.1 C22.1 C23.1 C33.1 C34.1 COUT5.P COUT6.P COUT7.1 COUT8.1 COUT9.1 COUT10.1 COUT11.1 COUT12.1 COUT16.1 COUT17.1 COUT19.1 COUT20.1 COUT25.1 COUT26.1 COUT27.1 COUT28.1 D1.3(C) J5.1(N1) Q1.3 Q1.5 Q1.7 R4.1 R17.2(N2) R67.1
VOUT2: C26.1 C27.1 C28.1 C29.1 C30.1 C31.1 C32.1 COUT1.1 COUT2.1 COUT3.P COUT4.P COUT13.1 COUT14.1 COUT15.1 COUT18.1 COUT21.1 COUT22.1 COUT23.1 COUT24.1 COUT29.1 COUT30.1 COUT31.1 COUT32.1 D2.3(C) J3.1(N1) Q4.3 Q4.5 Q4.7 R12.2(N2) R67.2(N2)

Pads without a net: P10 1; P11 1; P12 1; P13 1

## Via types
v1: diameter 0.305, hole 0.152, TOP to BOTTOM, 66 vias
v2: diameter 0.61, hole 0.254, TOP to BOTTOM, 549 vias

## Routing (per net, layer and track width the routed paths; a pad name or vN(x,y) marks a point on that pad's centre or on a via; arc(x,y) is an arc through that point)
GND_POWER: length 60.7
  TOP w0.254: 54.03,59.31 53.57,59.31
  LAYER_3 w0.254: v2(88.65,67.56) 88.39,67.56 87.88,68.07 87.88,82.93 91.19,86.23 96.01,86.23 97.79,88.01 E8.1 ; 72.48,8.76 72.52,8.8 ; E7.1 97.79,30.99 96.27,32.51 89.41,32.51 87.88,34.04 87.88,51.31 88.39,51.82 v2(88.65,51.82)
  vias: v1(65.53,67.84) v1(65.53,67.34) v1(65.53,66.78) v1(65.53,66.29) v1(65.53,53.11) v1(65.53,52.6) v1(65.53,52.04) v1(65.53,51.56) v1(66.55,67.87) v1(66.55,67.36) v1(66.55,66.8) v1(66.55,66.29) v1(66.55,53.14) v1(66.55,52.63) v1(66.55,52.07) v1(66.55,51.56) v1(67.54,67.87) v1(67.54,67.36) v1(67.54,66.8) v1(67.54,66.29) v1(67.54,53.14) v1(67.54,52.63) v1(67.54,52.07) v1(67.54,51.56) v2(1.91,110.49) v2(1.91,107.95) v2(1.91,105.41) v2(1.91,102.23) v2(1.91,99.06) v2(1.91,95.88) v2(1.91,92.71) v2(1.91,89.53) v2(1.91,86.36) v2(1.91,83.19) v2(1.91,80.01) v2(1.91,76.83) v2(1.91,74.3) v2(1.91,71.75) v2(1.91,68.58) v2(1.91,65.41) v2(1.91,62.23) v2(1.91,59.05) v2(1.91,55.88) v2(1.91,53.34) v2(1.91,50.8) v2(1.91,48.26) v2(1.91,45.72) v2(1.91,43.18) v2(1.91,40.64) v2(1.91,38.1) v2(1.91,35.56) v2(1.91,33.02) v2(1.91,30.48) v2(1.91,27.94) v2(1.91,25.4) v2(1.91,22.86) v2(1.91,20.32) v2(1.91,17.78) v2(1.91,15.24) v2(1.91,12.7) v2(1.91,10.16) v2(1.91,8.25) v2(4.45,109.85) v2(4.45,9.52) v2(7.62,110.49) v2(7.62,8.89) v2(8.89,1.91) v2(9.53,114.94) v2(9.53,112.39) v2(9.53,6.35) v2(9.53,3.81) v2(10.16,117.47) v2(13.34,117.47) v2(13.97,1.91) v2(16.51,117.47) v2(16.51,1.91) v2(19.05,1.91) v2(19.68,117.47) v2(21.59,1.91) v2(24.13,1.91) v2(26.67,1.91) v2(29.84,1.91) v2(32.38,1.91) v2(34.92,1.91) v2(37.47,1.91) v2(40.01,1.91) v2(41.91,34.42) v2(41.91,33.53) v2(41.91,32.51) v2(42.55,1.91) v2(42.93,34.42) v2(42.93,33.53) v2(43.81,34.42) v2(43.81,33.53) v2(44.7,34.42) v2(44.7,33.53) v2(45.09,1.91) v2(46.61,34.42) v2(46.61,33.53) v2(46.86,82.55) v2(47.37,34.42) v2(47.37,33.53) v2(47.62,82.55) v2(47.62,1.91) v2(48.39,88.65) v2(48.39,87.76) v2(48.39,86.87) v2(48.39,85.47) v2(48.39,84.58) v2(48.39,83.69) v2(49.15,88.65) v2(49.15,87.76) v2(49.15,86.87) v2(49.15,85.47) v2(49.15,84.58) v2(49.15,83.69) v2(50.16,1.91) v2(52.7,117.47) v2(52.7,114.55) v2(52.7,111.25) v2(52.7,103.76) v2(52.7,100.33) v2(52.7,1.91) v2(53.98,114.55) v2(53.98,111.25) v2(53.98,103.76) v2(53.98,100.33) v2(54.86,61.21) v2(54.86,59.69) v2(54.86,58.04) v2(55.24,114.55) v2(55.24,111.25) v2(55.24,103.76) v2(55.24,100.33) v2(55.24,1.91) v2(55.75,60.45) v2(55.75,58.8) v2(55.88,117.47) v2(56.39,114.55) v2(56.39,111.25) v2(56.39,103.76) v2(56.39,100.33) v2(56.64,61.21) v2(56.64,59.69) v2(56.64,58.04) v2(57.4,60.45) v2(57.53,58.8) v2(57.78,1.91) v2(58.17,61.21) v2(58.17,59.69) v2(58.17,58.04) v2(60.33,75.44) v2(60.33,43.56) v2(60.33,1.91) v2(61.09,76.71) v2(61.21,42.67) v2(61.98,76.71) v2(62.1,42.67) v2(62.61,50.55) v2(62.87,76.71) v2(62.87,42.67) v2(62.87,1.91) v2(63.12,65.28) v2(63.63,76.71) v2(63.63,42.67) v2(64.01,39.88) v2(64.26,79.5) v2(64.77,62.1) v2(64.9,64.26) v2(64.9,62.99) v2(64.9,55.88) v2(64.9,54.61) v2(65.15,80.52) v2(65.15,38.99) v2(65.41,1.91) v2(65.66,61.09) v2(66.17,80.52) v2(66.17,64.26) v2(66.17,62.99) v2(66.17,55.88) v2(66.17,54.61) v2(66.29,38.99) v2(67.06,80.52) v2(67.31,38.99) v2(67.44,64.26) v2(67.44,62.99) v2(67.44,59.05) v2(67.44,58.17) v2(67.44,57.28) v2(67.44,55.88) v2(67.44,54.61) v2(67.94,1.91) v2(68.07,80.52) v2(68.2,38.99) v2(68.33,59.05) v2(68.33,58.17) v2(68.71,64.26) v2(68.71,62.99) v2(68.71,55.88) v2(68.71,54.61) v2(69.09,80.52) v2(69.22,38.99) v2(69.34,59.05) v2(69.34,58.17) v2(69.98,64.26) v2(69.98,62.99) v2(69.98,55.88) v2(69.98,54.61) v2(70.1,80.52) v2(70.1,38.99) v2(70.48,1.91) v2(71.12,80.52) v2(71.12,38.99) v2(71.25,64.26) v2(71.25,62.99) v2(71.25,55.88) v2(71.25,54.61) v2(71.75,117.47) v2(71.75,61.59) v2(72.14,40.03) v2(72.14,38.99) v2(72.26,80.52) v2(72.26,79.38) v2(72.26,56.77) v2(72.52,64.26) v2(72.52,62.99) v2(72.52,55.88) v2(72.52,54.61) v2(73.03,1.91) v2(73.15,60.71) v2(73.28,57.78) v2(74.93,117.47) v2(75.31,60.71) v2(75.44,57.78) v2(75.56,1.91) v2(76.33,61.59) v2(76.58,56.9) v2(78.11,117.47) v2(78.11,1.91) v2(79.65,67.31) v2(80.64,67.34) v2(80.64,1.91) v2(81.28,117.47) v2(82.09,65.53) v2(82.09,54.1) v2(82.96,65.51) v2(82.96,54.08) v2(83.19,1.91) v2(83.79,65.51) v2(83.79,54.08) v2(84.45,117.47) v2(85.22,67.59) v2(85.24,53.95) v2(85.34,51.82) v2(85.39,65.53) v2(85.72,1.91) v2(86.13,67.56) v2(86.16,53.92) v2(86.23,51.82) v2(86.28,65.53) v2(87.07,67.56) v2(87.1,53.92) v2(87.12,51.82) v2(87.2,65.53) v2(88.27,1.91) v2(88.49,54) v2(88.65,65.53) v2(89.41,53.97) v2(89.53,67.56) v2(89.53,65.53) v2(89.53,51.82) v2(90.35,53.97) v2(90.42,67.56) v2(90.42,51.82) v2(90.55,65.53) v2(90.81,1.91) v2(92,65.53) v2(92,53.97) v2(92.86,65.51) v2(92.86,53.95) v2(93.34,1.91) v2(93.7,65.51) v2(93.7,53.95) v2(95.89,1.91) v2(98.3,58.04) v2(98.3,57.15) v2(98.42,65.02) v2(98.42,64.13) v2(98.42,63.25) v2(98.42,62.36) v2(98.42,61.47) v2(98.42,56.26) v2(98.42,55.37) v2(98.42,54.48) v2(98.42,1.91) v2(100.97,1.91) v2(101.47,58.04) v2(101.47,57.15) v2(101.6,65.02) v2(101.6,64.13) v2(101.6,63.25) v2(101.6,62.36) v2(101.6,61.47) v2(101.6,56.26) v2(101.6,55.37) v2(101.6,54.48) v2(103.5,1.91) v2(106.05,1.91) v2(108.58,1.91) v2(111.12,1.91) v2(113.67,1.91) v2(116.2,1.91) v2(118.11,6.35) v2(118.11,3.81) v2(118.75,1.91) v2(119.38,8.25) v2(121.28,9.52) v2(123.83,9.52) v2(125.09,109.85) v2(125.09,107.31) v2(125.09,104.78) v2(125.09,102.23) v2(125.09,99.69) v2(125.09,97.16) v2(125.09,94.61) v2(125.09,92.07) v2(125.09,89.53) v2(125.09,87) v2(125.09,84.45) v2(125.09,83.19) v2(125.09,80.64) v2(125.09,78.1) v2(125.09,75.56) v2(125.09,72.39) v2(125.09,69.85) v2(125.09,67.31) v2(125.09,64.77) v2(125.09,62.23) v2(125.09,59.69) v2(125.09,56.52) v2(125.09,53.97) v2(125.09,51.43) v2(125.09,48.26) v2(125.09,45.72) v2(125.09,43.18) v2(125.09,40) v2(125.09,36.19) v2(125.09,33.66) v2(125.09,31.11) v2(125.09,28.57) v2(125.09,26.03) v2(125.09,23.49) v2(125.09,20.95) v2(125.09,13.34) v2(125.09,10.79) v2(125.09,8.25)
GND_SIGNAL: length 139.4
  TOP w0.254: U1.6 52.1,59.31 v1(52.07,59.28) ; v2(46.74,56.13) 46.86,56.26 R36.2
  LAYER_5 w0.508: 14.86,45.59 16.13,45.59 v2(16.18,45.54) 16.18,47.96 v2(16.13,48.01) 21.59,53.47 21.59,61.21 ; 14.86,45.59 10.34,45.59 P3.3 ; 14.86,45.59 14.86,22.86 15.49,22.22 v2(16.36,22.22) v2(16.36,19.68) 15.8,19.68 15.77,19.66 10.34,19.66 P4.3 ; 6.13,68.49 4.83,67.18 4.83,63.63 6.22,62.23 20.57,62.23 21.59,61.21 ; 6.13,68.49 P2.3 ; 6.13,68.49 6.06,68.49 4.57,69.98 4.57,87.29 P1.5 ; 21.59,61.21 22.73,62.36 45.09,62.36
  BOTTOM w0.508: v2(16.18,45.54) 16.15,45.57 C24.2 ; R63.2 16.06,48.07 v2(16.13,48.01) ; v2(16.36,19.68) 16.33,19.66 C18.2 ; R58.2 16.29,22.16 v2(16.36,22.22)
  vias: v1(55.14,50.6) v2(48.26,63.37) v2(51.87,52.04) v2(56.82,66.4)
VIN: length 136.9
  TOP w0.254: v2(51.69,72.64) 51.64,72.59 R28.1 ; R25.1 v2(47.75,47.5)
  LAYER_3 w0.254: 21.03,25.63 21.03,47.22 17.68,50.57 v2(16.15,50.57) ; 21.03,25.63 21.69,24.97 39.06,24.97 v2(40.89,26.8) ; 21.03,25.63 17.32,25.63 v2(16.36,24.66) ; v2(52.58,26.67) 52.58,28.45 48.39,32.64 48.39,46.86 v2(47.75,47.5) ; v2(60.83,68.07) 59.94,67.18 45.97,67.18 43.05,70.1 v2(43.05,83.69) ; v2(52.45,92.71) 52.2,92.46 52.2,73.15 v2(51.69,72.64)
  BOTTOM w0.254: R2.1 60.94,67.96 v2(60.83,68.07) ; RS1.1 v2(52.45,92.71) ; v2(52.58,26.67) RS2.2
  BOTTOM w0.508: R62.1 15.85,50.57 15.85,50.57 v2(16.15,50.57) ; R56.2 16.35,24.66 v2(16.36,24.66)
  vias: v2(41.78,29.59) v2(41.78,28.7) v2(42.04,88.65) v2(42.04,87.76) v2(42.04,86.87) v2(42.16,85.47) v2(42.16,84.58) v2(42.16,83.69) v2(42.67,28.07) v2(42.67,27.18) v2(42.93,88.65) v2(42.93,87.76) v2(42.93,86.87) v2(43.05,85.47) v2(43.05,84.58) v2(43.56,28.07) v2(43.56,27.18) v2(44.45,28.07) v2(44.45,27.18) v2(47.24,28.07) v2(47.24,27.18) v2(48.13,28.07) v2(48.13,27.18)
EXTVCC: length 7.7
  TOP w0.254: U1.26 60.33,59.81 v1(60.35,59.79) 62.71,59.79 63.12,60.2 63.12,61.09 R46.1
  BOTTOM w0.254: v1(60.35,59.79) 60.38,59.82 62.61,59.82 62.99,59.44 R61.1
INTVCC: length 145.4
  TOP w0.254: U1.25 60.14,59.31 60.15,59.31 v1(60.86,59.31) 61.98,59.31 62.4,58.89 R35.2 64.69,58.89 C1.1
  TOP w0.508: v2(47.5,65.41) 48.01,65.91 R38.2
  LAYER_3 w0.508: v2(56.9,47.5) 58.17,47.5 62.23,51.56 62.23,58.55 61.47,59.31 ; v1(60.86,59.31) 61.47,59.31 ; 61.47,59.31 61.98,59.82 61.98,64.01 61.09,64.9 v2(59.69,64.9) 58.67,64.9 58.29,64.52 58.29,62.74 58.04,62.48 49.91,62.48 ; v2(46.99,57.91) 48.51,57.91 49.15,58.55 49.15,61.72 49.91,62.48 ; v2(47.5,65.41) 48.77,65.41 49.28,64.9 49.28,63.12 49.91,62.48
  LAYER_4 w0.508: 4.32,70.48 4.32,65.28 5.84,63.75 45.09,63.75 46.74,65.41 v2(47.5,65.41) ; 4.32,70.48 4.19,70.61 4.19,92.33 6.32,94.46 P1.1 ; 4.32,70.48 P2.1
  BOTTOM w0.254: v2(47.5,65.41) 46.48,64.39 R5.1
  BOTTOM w0.508: P1.1 5.35,94.46 R57.1 ; R47.1 58.29,48.89 v2(56.9,47.5) ; v2(46.99,57.91) R45.2 ; v2(59.69,64.9) 59.76,64.97 R44.2
PGOOD1: length 82
  TOP w0.254: R60.1 47.54,60.92 v2(47.37,61.09) ; U1.34 57.27,63.46 v1(57.25,63.47)
  LAYER_3 w0.254: 45.21,65.79 44.58,66.42 41.33,66.42 37.44,70.31 37.44,83.06 21.69,98.81 E2.1 ; 45.21,65.79 45.85,66.42 55.24,66.42 57.28,64.39 57.28,63.5 v1(57.25,63.47) ; 45.21,65.79 45.21,61.85 45.97,61.09 v2(47.37,61.09)
  BOTTOM w0.254: R5.2 46.52,61.09 v2(47.37,61.09)
PGOOD2: length 84.4
  TOP w0.254: R60.2 47.28,59.22 v2(47.24,59.18) ; v1(57.23,54.74) 57.27,54.78 U1.17
  LAYER_3 w0.254: v2(47.24,59.18) 45.97,59.18 45.47,58.67 45.47,57.66 45.97,57.15 49.28,57.15 50.42,56.01 57.02,56.01 57.53,55.5 57.53,54.99 57.28,54.74 v1(57.23,54.74)
  LAYER_4 w0.254: E1.1 34.67,7.09 34.67,38.23 46.61,50.16 52.65,50.16 v1(57.23,54.74)
  BOTTOM w0.254: R1.2 45.09,60.2 46.1,59.18 v2(47.24,59.18)
RUN1: length 61.4
  TOP w0.254: R64.1 50.58,60.32 v1(52.25,60.32) 53.5,60.32 U1.4
  LAYER_4 w0.254: E16.1 11.89,60.27 52.2,60.27 v1(52.25,60.32)
  BOTTOM w0.508: P3.2 6.78,48.54 5.84,49.48 5.84,54.23 E16.1
RUN2: length 78.2
  TOP w0.254: U1.5 52.63,59.81 v1(52.63,59.82) 50.58,59.82 R64.2
  LAYER_4 w0.254: v1(52.63,59.82) 53.29,59.82 53.85,59.26 53.85,57.66 54.36,57.15 54.36,56.39 52.7,54.74 44.7,54.74 20.83,30.86 E17.1
  BOTTOM w0.508: E17.1 6.36,29.6 6.36,29.48 5.46,28.57 5.46,23.49 6.35,22.61 P4.2
SENSE1+: length 42
  TOP w0.254: v2(68.22,93.01) 68.26,93.05 R30.2 ; U1.40 54.27,63.18 53.01,64.44 52.27,64.44 51.66,65.05 51.66,65.65 C7.2 ; 51.82,67.31 51.82,67.39 52.32,67.89 52.32,69.46 R28.2
  LAYER_3 w0.254: v2(51.69,68.45) 52.5,68.45 53.18,69.14 54.94,69.14 57.96,72.16 57.96,75.74 65.66,83.44 65.66,89.03 68.5,91.87 68.5,92.74 v2(68.22,93.01)
SENSE1-: length 41.6
  TOP w0.254: R29.2 52.83,69.56 52.83,67.79 53.21,67.41 53.21,67.31 ; R31.2 71.69,93.05 v2(71.73,93.01) ; U1.39 54.76,63.65 53.38,65.04 C7.1
  LAYER_3 w0.254: v2(53.47,68.45) 55.07,68.45 58.6,71.98 58.6,75.66 66.29,83.36 66.29,88.9 70.41,93.01 v2(71.73,93.01)
SENSE2+: length 47.4
  TOP w0.254: C5.1 47.73,52.32 48.26,51.79 48.26,50.29 47.97,50 R25.2 ; R27.2 69.09,25.65 v2(68.96,25.53) ; U1.11 54.27,56.12 53.39,55.24 48.64,55.24 47.66,54.27 R33.2
  LAYER_3 w0.254: v2(68.96,25.53) 68.96,26.29 64.77,30.48 64.77,35.56 49.66,50.67 49.02,50.67 48.26,51.43 v2(47.62,51.43)
SENSE2-: length 45.8
  TOP w0.254: R26.2 v2(70.87,25.53) ; U1.12 54.76,55.91 53.59,54.74 50.13,54.74 R33.1 ; R24.2 49.19,50 48.77,50.42 48.77,51.82 49.28,52.32 C5.2
  LAYER_3 w0.254: v2(49.4,51.43) 49.53,51.43 49.78,51.18 49.87,51.18 65.28,35.77 65.28,30.73 70.1,25.91 70.48,25.91 v2(70.87,25.53)
UNNAMED_2_ADLTC7892V2_I690_BGDN1: length 1.5
  TOP w0.254: U1.29 60.98,61.31
UNNAMED_2_ADLTC7892V2_I690_BGDN2: length 1.8
  TOP w0.254: 61.05,57.19 60.42,57.81 U1.22
UNNAMED_2_ADLTC7892V2_I690_BGUP1: length 2.1
  TOP w0.254: U1.28 61.57,60.81
UNNAMED_2_ADLTC7892V2_I690_BGUP2: length 1.9
  TOP w0.254: 61.29,57.96 60.94,58.31 U1.23
UNNAMED_2_ADLTC7892V2_I690_BOOST1: length 3.5
  TOP w0.254: v1(60.45,61.85) 60.42,61.81 U1.30
  BOTTOM w0.254: v1(60.45,61.85) 62.73,61.85 C3.2
UNNAMED_2_ADLTC7892V2_I690_BOOST2: length 1.9
  TOP w0.254: v1(60.33,56.77) 59.78,57.31 U1.21
  BOTTOM w0.254: C4.1 60.55,56.54 60.33,56.77 v1(60.33,56.77)
UNNAMED_2_ADLTC7892V2_I690_DRVCC: length 6
  TOP w0.254: U1.24 61.7,58.81 R35.1 64.56,57.19 C2.1
UNNAMED_2_ADLTC7892V2_I690_DRVSET: length 5.2
  TOP w0.254: U1.8 52.12,58.31 v1(52.07,58.27) 50.48,58.27 R3.1
  BOTTOM w0.254: v1(52.07,58.27) 51.12,58.27 R45.1
UNNAMED_2_ADLTC7892V2_I690_DRVUV: length 3
  TOP w0.254: v1(52.6,58.8) 52.62,58.81 U1.7
  BOTTOM w0.254: v1(52.6,58.8) 51.4,58.8 R54.1
UNNAMED_2_ADLTC7892V2_I690_DTCA: length 6.3
  TOP w0.254: R36.1 50.25,56.52 51.99,56.52 v1(52.37,56.9) 52.37,57.53 52.66,57.81 U1.9
  BOTTOM w0.254: v1(52.37,56.9) 51.14,56.9 R40.1
UNNAMED_2_ADLTC7892V2_I690_DTCB: length 3.7
  TOP w0.254: v1(53.34,56.9) 53.34,57.2 53.45,57.31 U1.10
  BOTTOM w0.254: R41.1 52.16,54.82 53.34,56.01 v1(53.34,56.9)
UNNAMED_2_ADLTC7892V2_I690_FREQ: length 4.4
  TOP w0.254: U1.1 53.35,61.81 53.14,62.03 53.11,62.03 50.88,64.26 R37.2
UNNAMED_2_ADLTC7892V2_I690_ILIM: length 4.3
  TOP w0.254: U1.16 56.76,55.35 v1(56.77,55.35)
  BOTTOM w0.254: 58.04,53.3 58.04,54.99 57.68,55.35 v1(56.77,55.35)
UNNAMED_2_ADLTC7892V2_I690_ITH1: length 4.1
  TOP w0.254: U1.37 55.76,63.74 v1(55.78,63.75)
  BOTTOM w0.254: C14.2 53.18,63.75 v1(55.78,63.75)
UNNAMED_2_ADLTC7892V2_I690_ITH2: length 3.9
  TOP w0.254: U1.14 55.76,55.13 55.5,54.86 55.5,53.23 55.19,52.91
UNNAMED_2_ADLTC7892V2_I690_MODE: length 62.3
  TOP w0.254: U1.2 52.68,61.31 v1(52.65,61.34)
  LAYER_4 w0.254: v1(52.65,61.34) 52.65,65.58 45.59,72.64 34.67,72.64 16.85,90.46 P1.6 P1.4 P1.2
UNNAMED_2_ADLTC7892V2_I690_SS2: length 4
  TOP w0.254: v1(56.18,54.74) 56.27,54.82 U1.15
  BOTTOM w0.254: v1(56.18,54.74) 56.18,54.06 C15.1
UNNAMED_2_ADLTC7892V2_I690_SW1: length 17.2
  TOP w0.178: Q1.6 66.54,70.63 ; Q2.5 66.04,67.31 ; Q2.7 67.04,67.29 ; 65.02,67.31 65.02,67.07 Q2.3 ; 65.54,70.65 Q1.4
  TOP w0.254: R31.1 v2(70.87,90.55)
  LAYER_2 w0.254: v1(64.64,69.34) v1(64.64,72.24)
  BOTTOM w0.254: v2(70.87,90.55) 70.61,90.55 70.23,90.17 70.23,88.77 70.87,88.14 72.64,88.14 L1.1 ; v1(59.31,62.74) 59.41,62.84 59.42,62.84 59.92,63.33 C3.1
  vias: v1(59.31,63.12) v1(64.16,70.43) v2(71.63,70.99) v2(71.63,69.98) v2(71.63,69.09) v2(72.64,70.99) v2(72.64,69.98) v2(72.64,69.09) v2(73.66,70.99) v2(73.66,69.98) v2(73.66,69.09) v2(74.68,70.99) v2(74.68,69.98) v2(74.68,69.09) v2(75.69,70.99) v2(75.69,69.98) v2(75.69,69.09) v2(77.85,87.5) v2(77.85,86.36) v2(77.85,85.22) v2(77.85,84.07) v2(78.87,87.5) v2(78.87,86.36) v2(78.87,85.22) v2(78.87,84.07) v2(79.88,87.5) v2(79.88,86.36) v2(79.88,85.22) v2(79.88,84.07) v2(80.9,87.5) v2(80.9,86.36) v2(80.9,85.22) v2(80.9,84.07)
UNNAMED_2_ADLTC7892V2_I690_SW2: length 15.8
  TOP w0.178: 65.54,48.76 Q4.4 ; 66.54,48.76 Q4.6
  TOP w0.203: Q3.3 65.04,52.09 ; Q4.2 64.54,47.14 v1(64.52,47.12) ; Q3.7 67.04,52.09 ; Q3.5 66.04,52.07
  TOP w0.254: R26.1 v2(70.87,28.83)
  LAYER_2 w0.254: v1(64.52,49.78) v1(64.52,47.12)
  BOTTOM w0.254: L2.2 72.64,30.99 70.74,30.99 70.23,30.48 70.23,29.08 70.48,28.83 v2(70.87,28.83) ; C4.2 59.73,54.32 59.05,54.99 v1(59.05,55.12)
  vias: v1(59.05,55.63) v1(64.03,47.96) v2(71.63,50.29) v2(71.63,49.4) v2(71.63,48.39) v2(72.64,50.29) v2(72.64,49.4) v2(72.64,48.39) v2(73.66,50.29) v2(73.66,49.4) v2(73.66,48.39) v2(74.68,50.29) v2(74.68,49.4) v2(74.68,48.39) v2(75.69,50.29) v2(75.69,49.4) v2(75.69,48.39) v2(77.6,35.18) v2(77.6,34.04) v2(77.6,32.89) v2(77.6,31.75) v2(78.61,35.18) v2(78.61,34.04) v2(78.61,32.89) v2(78.61,31.75) v2(79.63,35.18) v2(79.63,34.04) v2(79.63,32.89) v2(79.63,31.75) v2(80.64,35.18) v2(80.64,34.04) v2(80.64,32.89) v2(80.64,31.75)
UNNAMED_2_ADLTC7892V2_I690_TGDN1: length 0.7
  TOP w0.254: U1.32 58.27,63.27
UNNAMED_2_ADLTC7892V2_I690_TGDN2: length 1.7
  TOP w0.254: U1.19 58.27,54.89 58.29,54.86
UNNAMED_2_ADLTC7892V2_I690_TGUP1: length 1.3
  TOP w0.254: U1.33 57.76,63.86
UNNAMED_2_ADLTC7892V2_I690_TGUP2: length 3.7
  TOP w0.254: U1.18 57.76,52.85
UNNAMED_2_ADLTC7892V2_I690_VBIAS: length 18.2
  TOP w0.254: R4.2 v2(58.93,70.74) ; U1.27 60.82,60.31 v1(60.83,60.32)
  LAYER_4 w0.254: v1(60.83,60.32) 61.47,60.96 61.47,63.37 60.71,64.13 v1(59.56,64.13) 59.31,64.13 58.29,65.15 58.29,70.23 58.8,70.74 v2(58.93,70.74)
  BOTTOM w0.254: v1(59.56,64.13) 60.2,64.13 60.94,64.88 R2.2 ; v1(60.83,60.32) 61.34,60.83 C25.1
UNNAMED_2_ADLTC7892V2_I690_VPRG1: length 6
  TOP w0.254: U1.35 v1(56.76,63.75)
  BOTTOM w0.254: R43.1 58.26,65.74 R44.1 58.06,65.05 v1(56.76,63.75)
UNNAMED_2_CAP_I201_N1: length 60.1
  TOP w0.254: C16.1 51.78,60.83 v1(51.84,60.83) 51.86,60.81 U1.3
  LAYER_4 w0.254: P2.6 50.35,66.49 51.05,65.79 51.05,61.34 51.56,60.83 v1(51.84,60.83)
  BOTTOM w0.254: R49.2 9.79,70.52 P2.2 P2.4 P2.6 P2.5
UNNAMED_2_CAP_I211_N1: length 3.5
  TOP w0.254: U1.36 v1(56.27,63.47)
  BOTTOM w0.254: 55.16,65.63 55.16,65.49 56.26,64.39 56.26,63.47 v1(56.27,63.47)
UNNAMED_2_CAP_I718_N1: length 4.2
  BOTTOM w0.508: R62.2 13.55,50.57 9.43,50.57 P3.1
UNNAMED_2_CAP_I719_N1: length 4.2
  BOTTOM w0.508: P4.1 9.43,24.64 13.53,24.64 R56.1
UNNAMED_2_CN6PODDEVEN_I358_N3: length 2.6
  BOTTOM w0.508: P1.3 5.37,92.46 R57.2
UNNAMED_2_CNBNC5P_I602_CNTR: length 3.5
  BOTTOM w0.254: v1(64.14,71.15) 64.44,71.15
  BOTTOM w0.381: 64.44,71.15 65.48,70.1 J7.1
  vias: v1(64.14,71.53)
UNNAMED_2_CNBNC5P_I603_CNTR: length 2.9
  BOTTOM w0.381: J8.1 67.06,49.15 64.33,49.15
  vias: v1(64.06,49.23) v1(64.06,48.84)
UNNAMED_2_CNTP1P_I84_N1: length 7.9
  BOTTOM w0.254: R49.1 12.7,74.68 11.81,75.56 E10.1
UNNAMED_2_CNTP1P_I85_N1: length 68.1
  LAYER_4 w0.254: E11.1 16.13,98.17 35.56,78.74 51.69,78.74 55.12,75.31 v2(55.12,71.63)
  BOTTOM w0.254: R52.1 v2(55.12,71.63)
UNNAMED_2_CNTP1P_I261_N1: length 73.9
  LAYER_4 w0.254: v2(63.25,56.13) 54.36,47.24 54.36,45.08 52.32,43.05 44.45,43.05 38.73,37.34 38.73,13.21 45.34,6.6 E12.1
  BOTTOM w0.254: R61.2 63.25,57.32 v2(63.25,56.13)
UNNAMED_2_CNTP1P_I280_N1: length 65.6
  LAYER_4 w0.254: v1(52.83,54.23) 52.83,53.97 52.58,53.72 47.5,53.72 26.67,32.89 26.67,13.84 19.43,6.6 E9.1
  BOTTOM w0.254: R50.2 53.09,54.48 v1(52.83,54.23)
UNNAMED_2_IND_I545_N2: length 32
  TOP w0.254: R29.1 53.42,72.57 v2(53.34,72.64) ; R30.1 v2(69.09,90.55)
  LAYER_3 w0.254: v2(53.85,92.71) 53.47,92.71 52.7,91.95 52.7,73.28 v2(53.34,72.64)
  BOTTOM w0.254: L1.2 64.9,85.6 67.44,88.14 69.09,88.14 69.72,88.77 69.72,90.17 69.34,90.55 v2(69.09,90.55) ; v2(53.85,92.71) RS1.2
UNNAMED_2_IND_I546_N1: length 33.9
  TOP w0.254: R27.1 v2(69.09,28.83) ; R24.1 v2(49.4,47.5)
  LAYER_3 w0.254: v2(54.1,26.67) 53.16,27.61 53.16,28.63 48.9,32.89 48.9,46.99 v2(49.4,47.5)
  BOTTOM w0.254: L2.1 67.31,30.99 69.09,30.99 69.72,30.35 69.72,29.08 69.47,28.83 v2(69.09,28.83) ; v2(54.1,26.67) RS2.1
UNNAMED_2_RES_I628_N1:
  vias: v1(64.26,67.77) v1(64.26,67.39) v2(63.5,67.56)
UNNAMED_2_RES_I641_N2:
  vias: v1(64.01,53.04) v1(64.01,52.65) v2(63.5,52.83)
VFB1: length 3.1
  TOP w0.254: U1.38 55.27,65.35 C8.1
VFB2: length 4.6
  TOP w0.254: U1.13 55.27,55.52 53.47,53.72 53.47,52.74 C13.1
VOSP1: length 83.4
  LAYER_3 w0.254: E6.1 97.79,80.77 101.98,84.96 101.98,93.32 99.19,96.11 64.87,96.11 61.72,92.96 61.72,82.8 56.87,77.95 v2(56.87,72.69)
  BOTTOM w0.254: R17.1 E6.1
VOSP2: length 85.3
  LAYER_3 w0.254: E5.1 98.68,38.86 101.98,35.56 101.98,26.85 98.17,23.04 65.61,23.04 60.96,27.69 60.96,37.49 51.77,46.69 v2(51.77,46.81)
  BOTTOM w0.254: R12.1 E5.1
VOUT1: length 22.5
  TOP w0.178: 65.04,71.09 Q1.3 ; Q1.5 66.04,71.07 ; Q1.7 67.04,71.05
  LAYER_3 w0.254: v2(96.65,85.47) 91.31,85.47 88.52,82.68 88.52,71.3 v2(88.57,71.25)
  BOTTOM w0.254: v2(96.65,85.47) 96.73,85.56 R17.2
  vias: v2(61.59,72.9) v2(62.48,72.9) v2(63.37,72.9) v2(64.52,74.42) v2(64.52,73.53) v2(65.41,74.42) v2(65.41,73.53) v2(66.67,75.56) v2(66.67,74.68) v2(66.67,73.79) v2(66.67,72.9) v2(68.33,75.56) v2(68.33,74.68) v2(68.33,73.79) v2(68.33,72.9) v2(69.85,75.56) v2(69.85,74.68) v2(69.85,73.79) v2(69.85,72.9) v2(71.63,75.56) v2(71.63,74.68) v2(71.63,73.79) v2(71.63,72.9) v2(82.09,71.37) v2(82.96,71.35) v2(83.79,71.35) v2(85.27,68.88) v2(85.39,71.37) v2(86.16,68.88) v2(86.26,71.35) v2(87.1,71.35) v2(87.07,68.86) v2(88.62,68.88) v2(89.48,71.22) v2(89.53,68.86) v2(90.42,71.22) v2(90.47,68.86) v2(92,71.25) v2(92.86,71.22) v2(93.7,71.22)
VOUT2: length 24.9
  TOP w0.178: 65.04,48.28 Q4.3 ; Q4.5 66.04,48.26 ; Q4.7 67.04,48.28
  LAYER_3 w0.254: v2(88.62,48.54) 88.52,48.44 88.52,34.42 89.79,33.15 96.44,33.15 v2(96.85,33.55)
  BOTTOM w0.254: R12.2 96.86,33.57 v2(96.85,33.55)
  vias: v2(61.34,46.48) v2(62.23,46.48) v2(63.25,46.48) v2(64.52,45.77) v2(64.52,45.01) v2(65.28,45.77) v2(65.28,45.01) v2(66.67,45.87) v2(66.67,45.11) v2(66.67,44.22) v2(66.67,43.46) v2(68.33,45.87) v2(68.33,45.11) v2(68.33,44.22) v2(68.33,43.46) v2(69.85,45.87) v2(69.85,45.11) v2(69.85,44.22) v2(69.85,43.46) v2(71.63,45.85) v2(71.63,45.08) v2(71.63,44.2) v2(71.63,43.43) v2(82.09,48.64) v2(82.96,48.62) v2(83.79,48.62) v2(85.29,50.52) v2(85.34,48.54) v2(86.18,50.52) v2(86.23,48.54) v2(87.1,50.5) v2(87.15,48.51) v2(88.65,50.55) v2(89.46,50.52) v2(89.53,48.51) v2(90.37,50.5) v2(90.47,48.51) v2(92,48.51) v2(92.86,48.49) v2(93.7,48.49)

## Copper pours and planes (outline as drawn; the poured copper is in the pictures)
GND_POWER on TOP: 1.02,118.36 1.02,1.02 125.98,1.02 125.98,118.36 ; 2 cut-outs
GND_POWER on BOTTOM: 1.02,118.36 1.02,0.89 125.98,0.89 125.98,118.36 ; 2 cut-outs
GND_POWER on LAYER_2: 1.02,118.36 1.02,1.02 125.98,1.02 125.98,118.36 ; 4 cut-outs
GND_POWER on LAYER_3: 1.02,118.36 1.02,1.02 125.98,1.02 125.98,118.36 ; 4 cut-outs
GND_POWER on LAYER_4: 1.02,118.36 1.02,0.89 125.98,0.89 125.98,118.36 ; 4 cut-outs
GND_POWER on LAYER_5: 1.02,118.36 1.02,0.89 125.98,0.89 125.98,118.36 ; 8 cut-outs
GND_SIGNAL on TOP: 47.75,58.42 47.75,55.63 48.77,55.63 48.77,58.42
GND_SIGNAL on TOP: 56.13,67.82 56.13,65.02 57.28,65.02 57.28,67.82
GND_SIGNAL on TOP: 47.62,64.9 47.62,61.98 48.9,61.98 48.9,64.9
GND_SIGNAL on TOP: 51.28,53.29 51.28,50.75 52.43,50.75 52.43,53.29
GND_SIGNAL on TOP: 54.61,51.66 54.61,49.33 55.75,49.33 55.75,51.66
GND_SIGNAL on BOTTOM: 50.93,53.59 50.93,51.69 52.2,51.69 52.2,53.59
GND_SIGNAL on BOTTOM: 53.09,51.94 57.28,51.94 57.28,49.91 53.09,49.91
GND_SIGNAL on BOTTOM: 47.37,64.26 47.37,61.85 48.51,61.85 48.51,60.32 49.53,60.32 49.53,61.85 51.94,61.85 51.94,63.12 48.9,63.12 48.9,64.77 47.88,64.77
GND_SIGNAL on BOTTOM: 56.13,67.82 56.13,65.15 57.28,65.15 57.28,66.67 58.55,66.67 58.55,67.82
GND_SIGNAL on LAYER_5: 44.75,70.1 44.75,47.93 63.88,47.93 63.88,70.1
VIN on TOP: 21.72,118.36 21.72,82.17 45.72,82.17 45.72,118.36
VIN on BOTTOM: 23.88,118.36 23.88,29.59 30.1,23.37 52.32,23.37 52.32,30.35 42.55,30.35 39.37,33.53 39.37,76.07 45.47,82.17 45.47,88.65 46.23,89.41 52.07,89.41 52.07,118.36
INTVCC on TOP: 56.13,49.02 56.13,46.99 57.4,46.99 57.4,49.02
INTVCC on BOTTOM: 47.88,56.01 47.88,54.1 49.15,54.1 49.15,55.37 49.4,55.63 49.59,55.63 49.59,59.94 48.39,59.94 48.39,56.52
INTVCC on BOTTOM: 44.51,63.37 44.51,62.36 46.99,62.36 46.99,63.37
SENSE1+ on TOP: 51.18,68.96 51.18,65.15 52.07,65.15 52.07,67.82 51.99,67.89 51.99,68.96
SENSE1- on TOP: 53.16,68.96 53.16,68 52.98,67.82 52.98,65.15 53.98,65.15 53.98,68.96
SENSE2+ on TOP: 47.12,54.61 47.12,51.05 47.93,51.05 47.93,51.69 48.06,51.82 48.06,54.61
SENSE2- on TOP: 49.1,51.69 49.1,51.05 49.91,51.05 49.91,54.61 48.97,54.61 48.97,51.82
UNNAMED_2_ADLTC7892V2_I690_BGDN1 on TOP (solid shape): 62.48,67.06 61.72,67.06 61.34,66.67 61.34,63.37 61.47,63.25 61.47,61.47 61.21,61.21 60.83,61.21 60.83,61.47 60.96,61.59 60.96,62.74 60.71,62.99 60.71,67.06 61.59,67.94 62.48,67.94
UNNAMED_2_ADLTC7892V2_I690_BGDN2 on TOP (solid shape): 61.34,57.02 61.34,52.43 61.57,52.2 62.48,52.2 62.48,51.43 60.96,51.43 60.71,51.69 60.71,57.28 60.9,57.47
UNNAMED_2_ADLTC7892V2_I690_BGUP1 on TOP (solid shape): 62.36,60.83 62.1,60.58 61.47,60.58 61.34,60.71 61.34,60.96 61.47,60.96 61.72,61.21 61.72,66.67 62.36,66.67
UNNAMED_2_ADLTC7892V2_I690_BGUP2 on TOP (solid shape): 62.48,57.15 62.48,52.45 61.72,52.45 61.72,57.15 60.96,57.91 60.96,58.17 61.47,58.17
UNNAMED_2_ADLTC7892V2_I690_DRVUV on BOTTOM: 50.16,61.47 50.16,58.93 51.31,58.93 51.31,61.47
UNNAMED_2_ADLTC7892V2_I690_DTCB on BOTTOM: 49.53,55.37 49.53,54.23 52.2,54.23 52.2,55.37
UNNAMED_2_ADLTC7892V2_I690_FREQ on TOP: 49.4,66.55 49.4,63.63 50.67,63.63 50.67,66.55
UNNAMED_2_ADLTC7892V2_I690_ILIM on BOTTOM: 56.13,53.59 56.13,52.58 58.8,52.58 58.8,53.59
UNNAMED_2_ADLTC7892V2_I690_ITH1 on BOTTOM: 52.45,64.52 52.45,61.72 53.59,61.72 53.59,64.52
UNNAMED_2_ADLTC7892V2_I690_ITH2 on TOP: 54.58,53.42 54.58,52.45 57.28,52.45 57.28,53.42
UNNAMED_2_ADLTC7892V2_I690_SS2 on BOTTOM: 53.21,53.59 53.21,52.45 55.75,52.45 55.75,54.99 54.74,54.99 54.74,54.1 54.23,53.59
UNNAMED_2_ADLTC7892V2_I690_SW1 on TOP (solid shape): 59.75,62.93 58.86,62.04 58.62,62.04 58.62,62.81 59.44,63.63 59.75,63.63
UNNAMED_2_ADLTC7892V2_I690_SW1 on TOP: 67.16,67.13 67.16,68.33 79.88,68.33 79.88,71.88 67.31,71.88 67.31,70.74 63.75,70.74 63.75,69.6 62.74,69.6 62.74,68.2 64.92,68.2 64.92,67.13
UNNAMED_2_ADLTC7892V2_I690_SW1 on BOTTOM: 59.05,63.25 59.05,62.48 59.44,62.48 60.2,63.25 60.2,63.5 59.31,63.5
UNNAMED_2_ADLTC7892V2_I690_SW1 on BOTTOM: 63.75,70.74 64.39,70.74 65.28,69.85 65.28,69.27 65.02,69.27 64.95,69.34 64.93,69.34 64.84,69.54 64.64,69.63 64.58,69.62 64.52,69.6 63.75,70.36
UNNAMED_2_ADLTC7892V2_I690_SW1 on BOTTOM: 65.02,72.06 79.88,72.06 79.88,68.33 69.6,68.33 69.6,72.03 69.34,72.03 69.34,68.33 65.02,68.33
UNNAMED_2_ADLTC7892V2_I690_SW1 on BOTTOM: 73.15,88.01 73.15,83.19 81.41,83.19 81.41,88.01
UNNAMED_2_ADLTC7892V2_I690_SW1 on LAYER_2: 64.64,72.26 64.64,69.47 64.52,69.47 64.52,69.85 61.21,69.85 59.05,67.69 59.05,63.37 59.56,63.37 59.56,62.36 57.53,62.36 57.53,68.45 60.83,71.75 64.52,71.75 64.52,72.26 ; 1 cut-out
UNNAMED_2_ADLTC7892V2_I690_SW1 on LAYER_3: 69.22,67.97 76.1,67.97 81.41,73.28 81.41,88.01 77.34,88.01 73.41,84.07 73.41,72.31 69.22,72.31
UNNAMED_2_ADLTC7892V2_I690_SW1 on LAYER_4: 69.22,67.94 76.07,67.94 81.28,73.15 81.28,88.39 77.72,88.39 73.41,84.07 73.41,72.26 69.22,72.26
UNNAMED_2_ADLTC7892V2_I690_SW2 on TOP (solid shape): 59.5,56.4 59.5,54.93 58.74,54.93 58.74,55.56 58.62,55.68 58.62,57.09 58.81,57.09
UNNAMED_2_ADLTC7892V2_I690_SW2 on TOP: 79.88,47.5 79.88,51.05 67.16,51.05 67.16,52.25 64.92,52.25 64.92,50.67 64.29,50.04 64.29,49.53 64.77,49.53 64.77,48.64 67.39,48.64 67.39,47.5
UNNAMED_2_ADLTC7892V2_I690_SW2 on BOTTOM: 63.83,48.31 63.83,47.5 65.18,47.5 65.18,48.31
UNNAMED_2_ADLTC7892V2_I690_SW2 on BOTTOM: 65.02,51.05 79.88,51.05 79.88,47.5 69.47,47.5 69.47,51.03 69.22,51.03 69.22,47.5 65.02,47.5
UNNAMED_2_ADLTC7892V2_I690_SW2 on BOTTOM: 73.03,35.94 73.03,30.99 81.15,30.99 81.15,35.94
